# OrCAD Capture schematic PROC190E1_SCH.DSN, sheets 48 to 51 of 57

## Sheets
48 48. TEMPERATURE SENSOR & BRD ID: size C; title: TEMPERATURE SENSORS & BOARD ID EEPROM
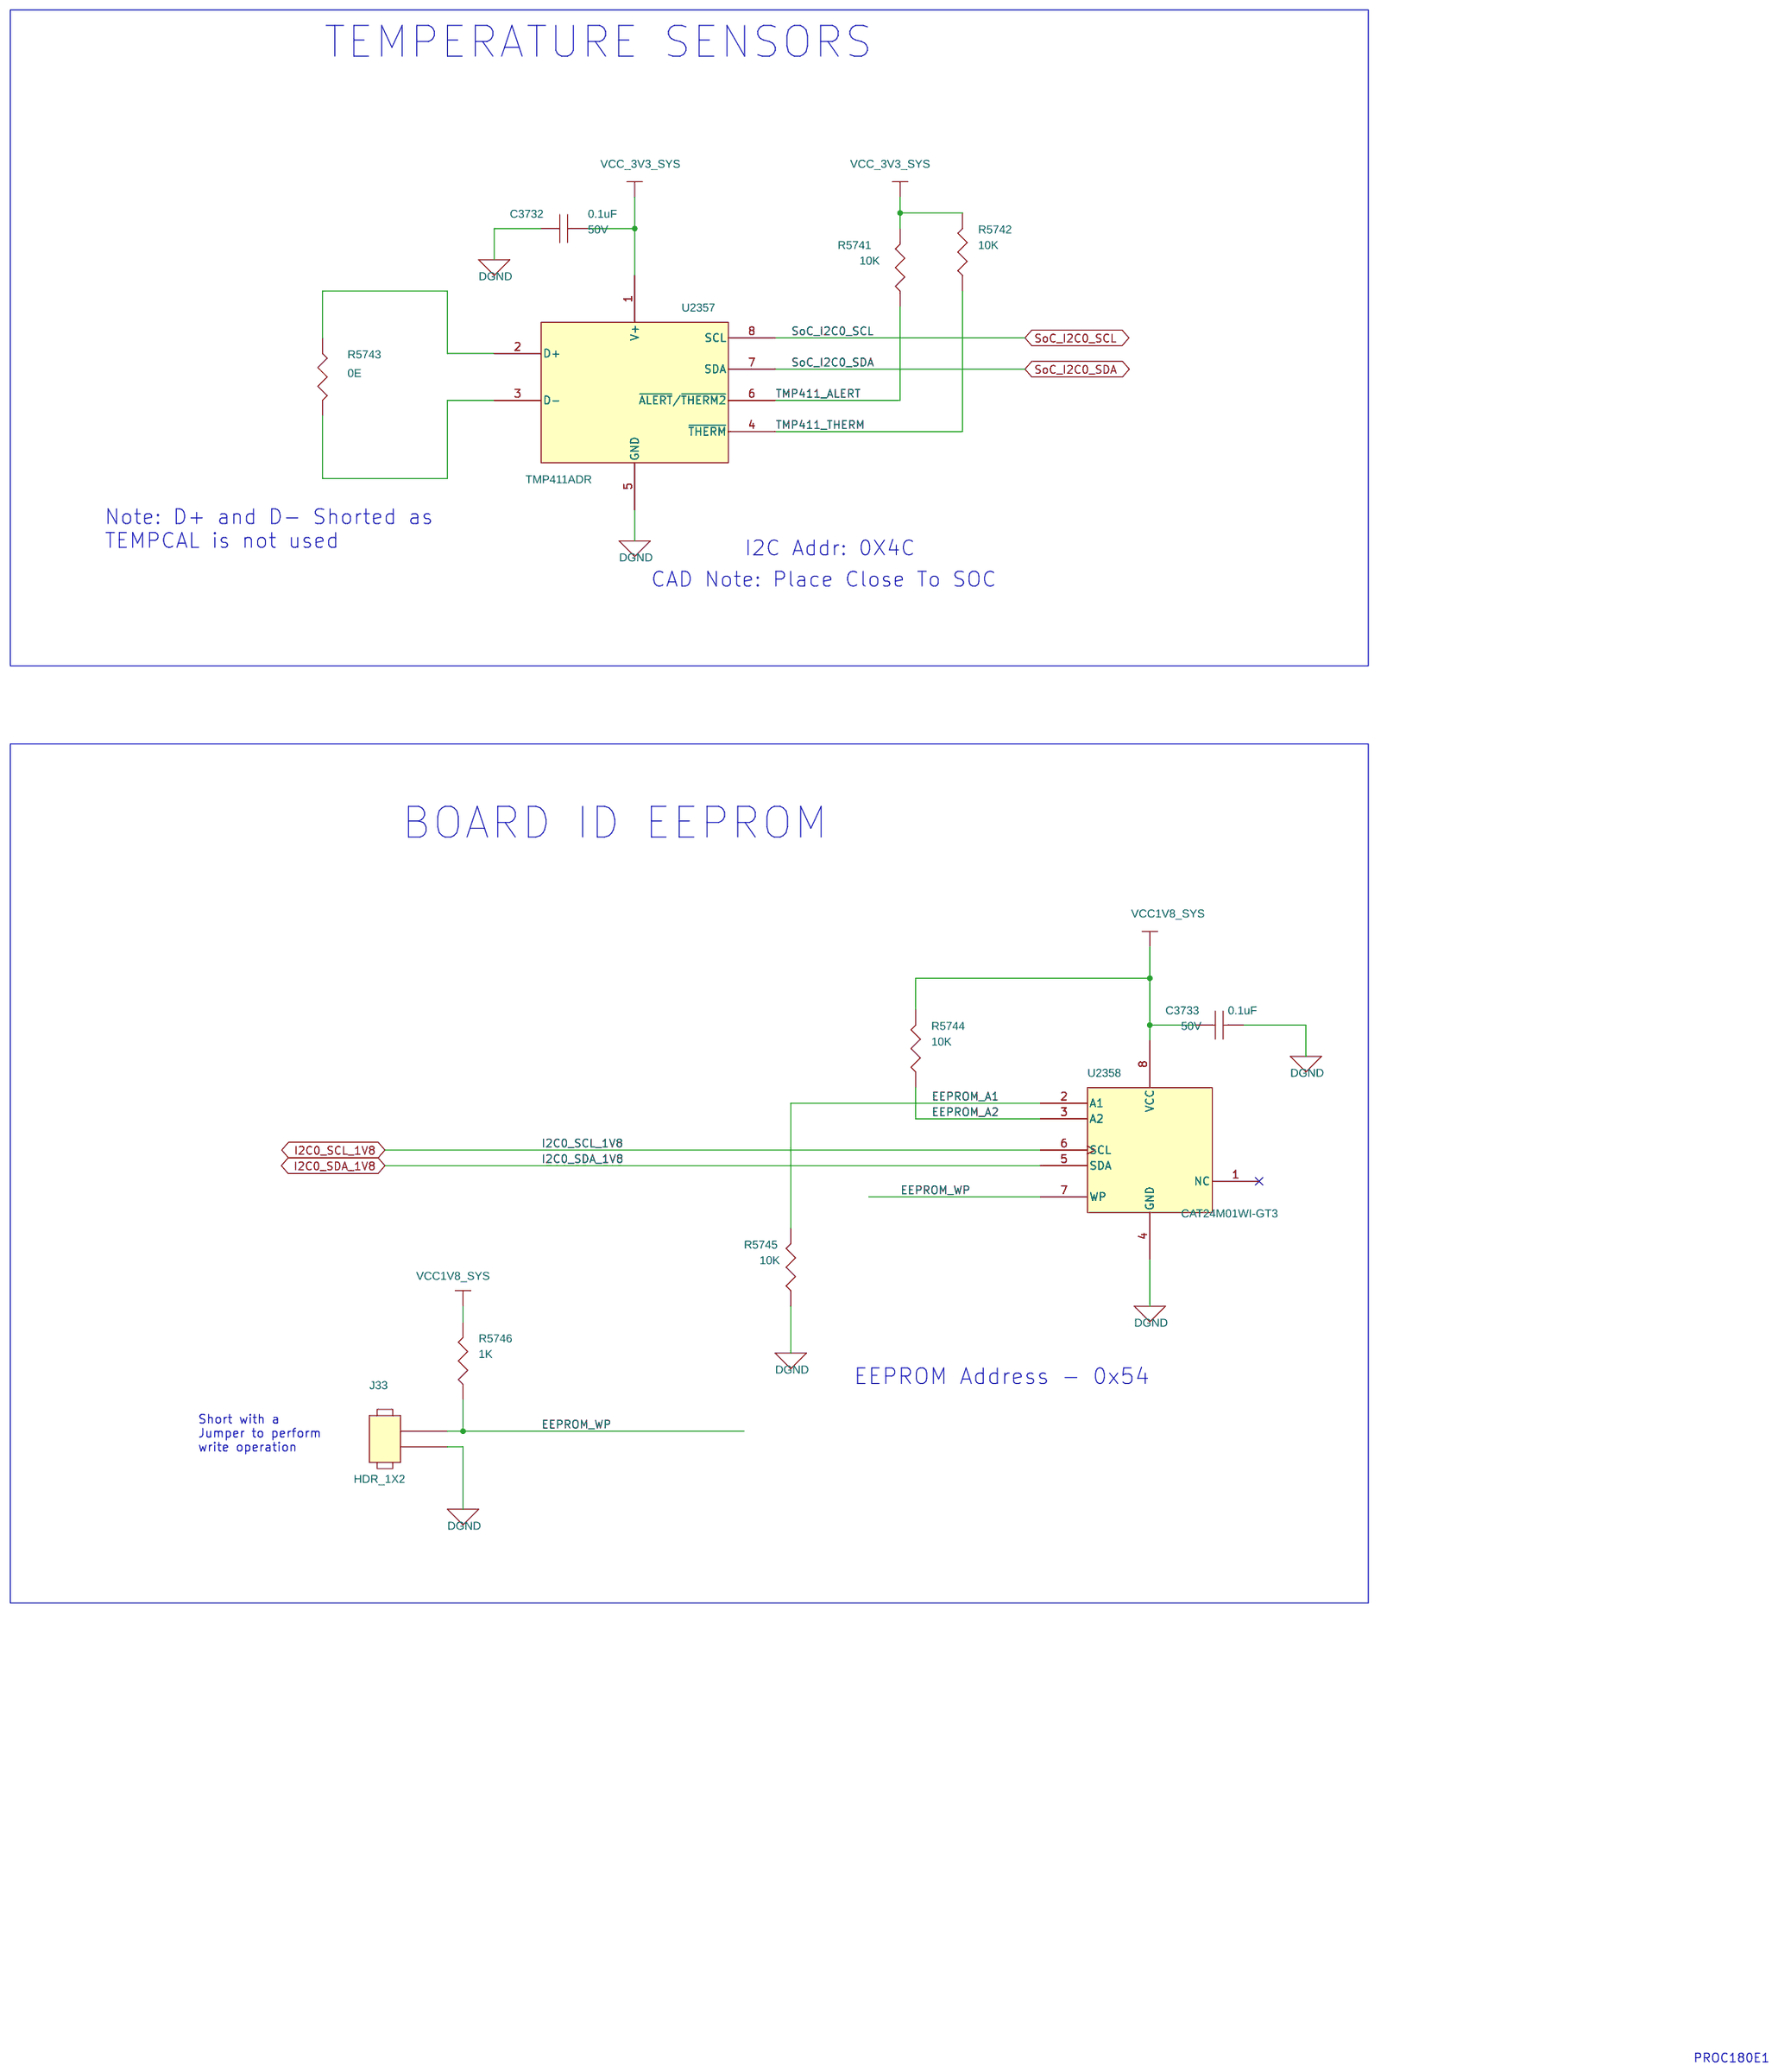
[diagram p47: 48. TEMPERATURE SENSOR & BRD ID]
49 49. CURRENT MONITORING - 1: size C; title: CURRENT MONITORING DEVICES - 1
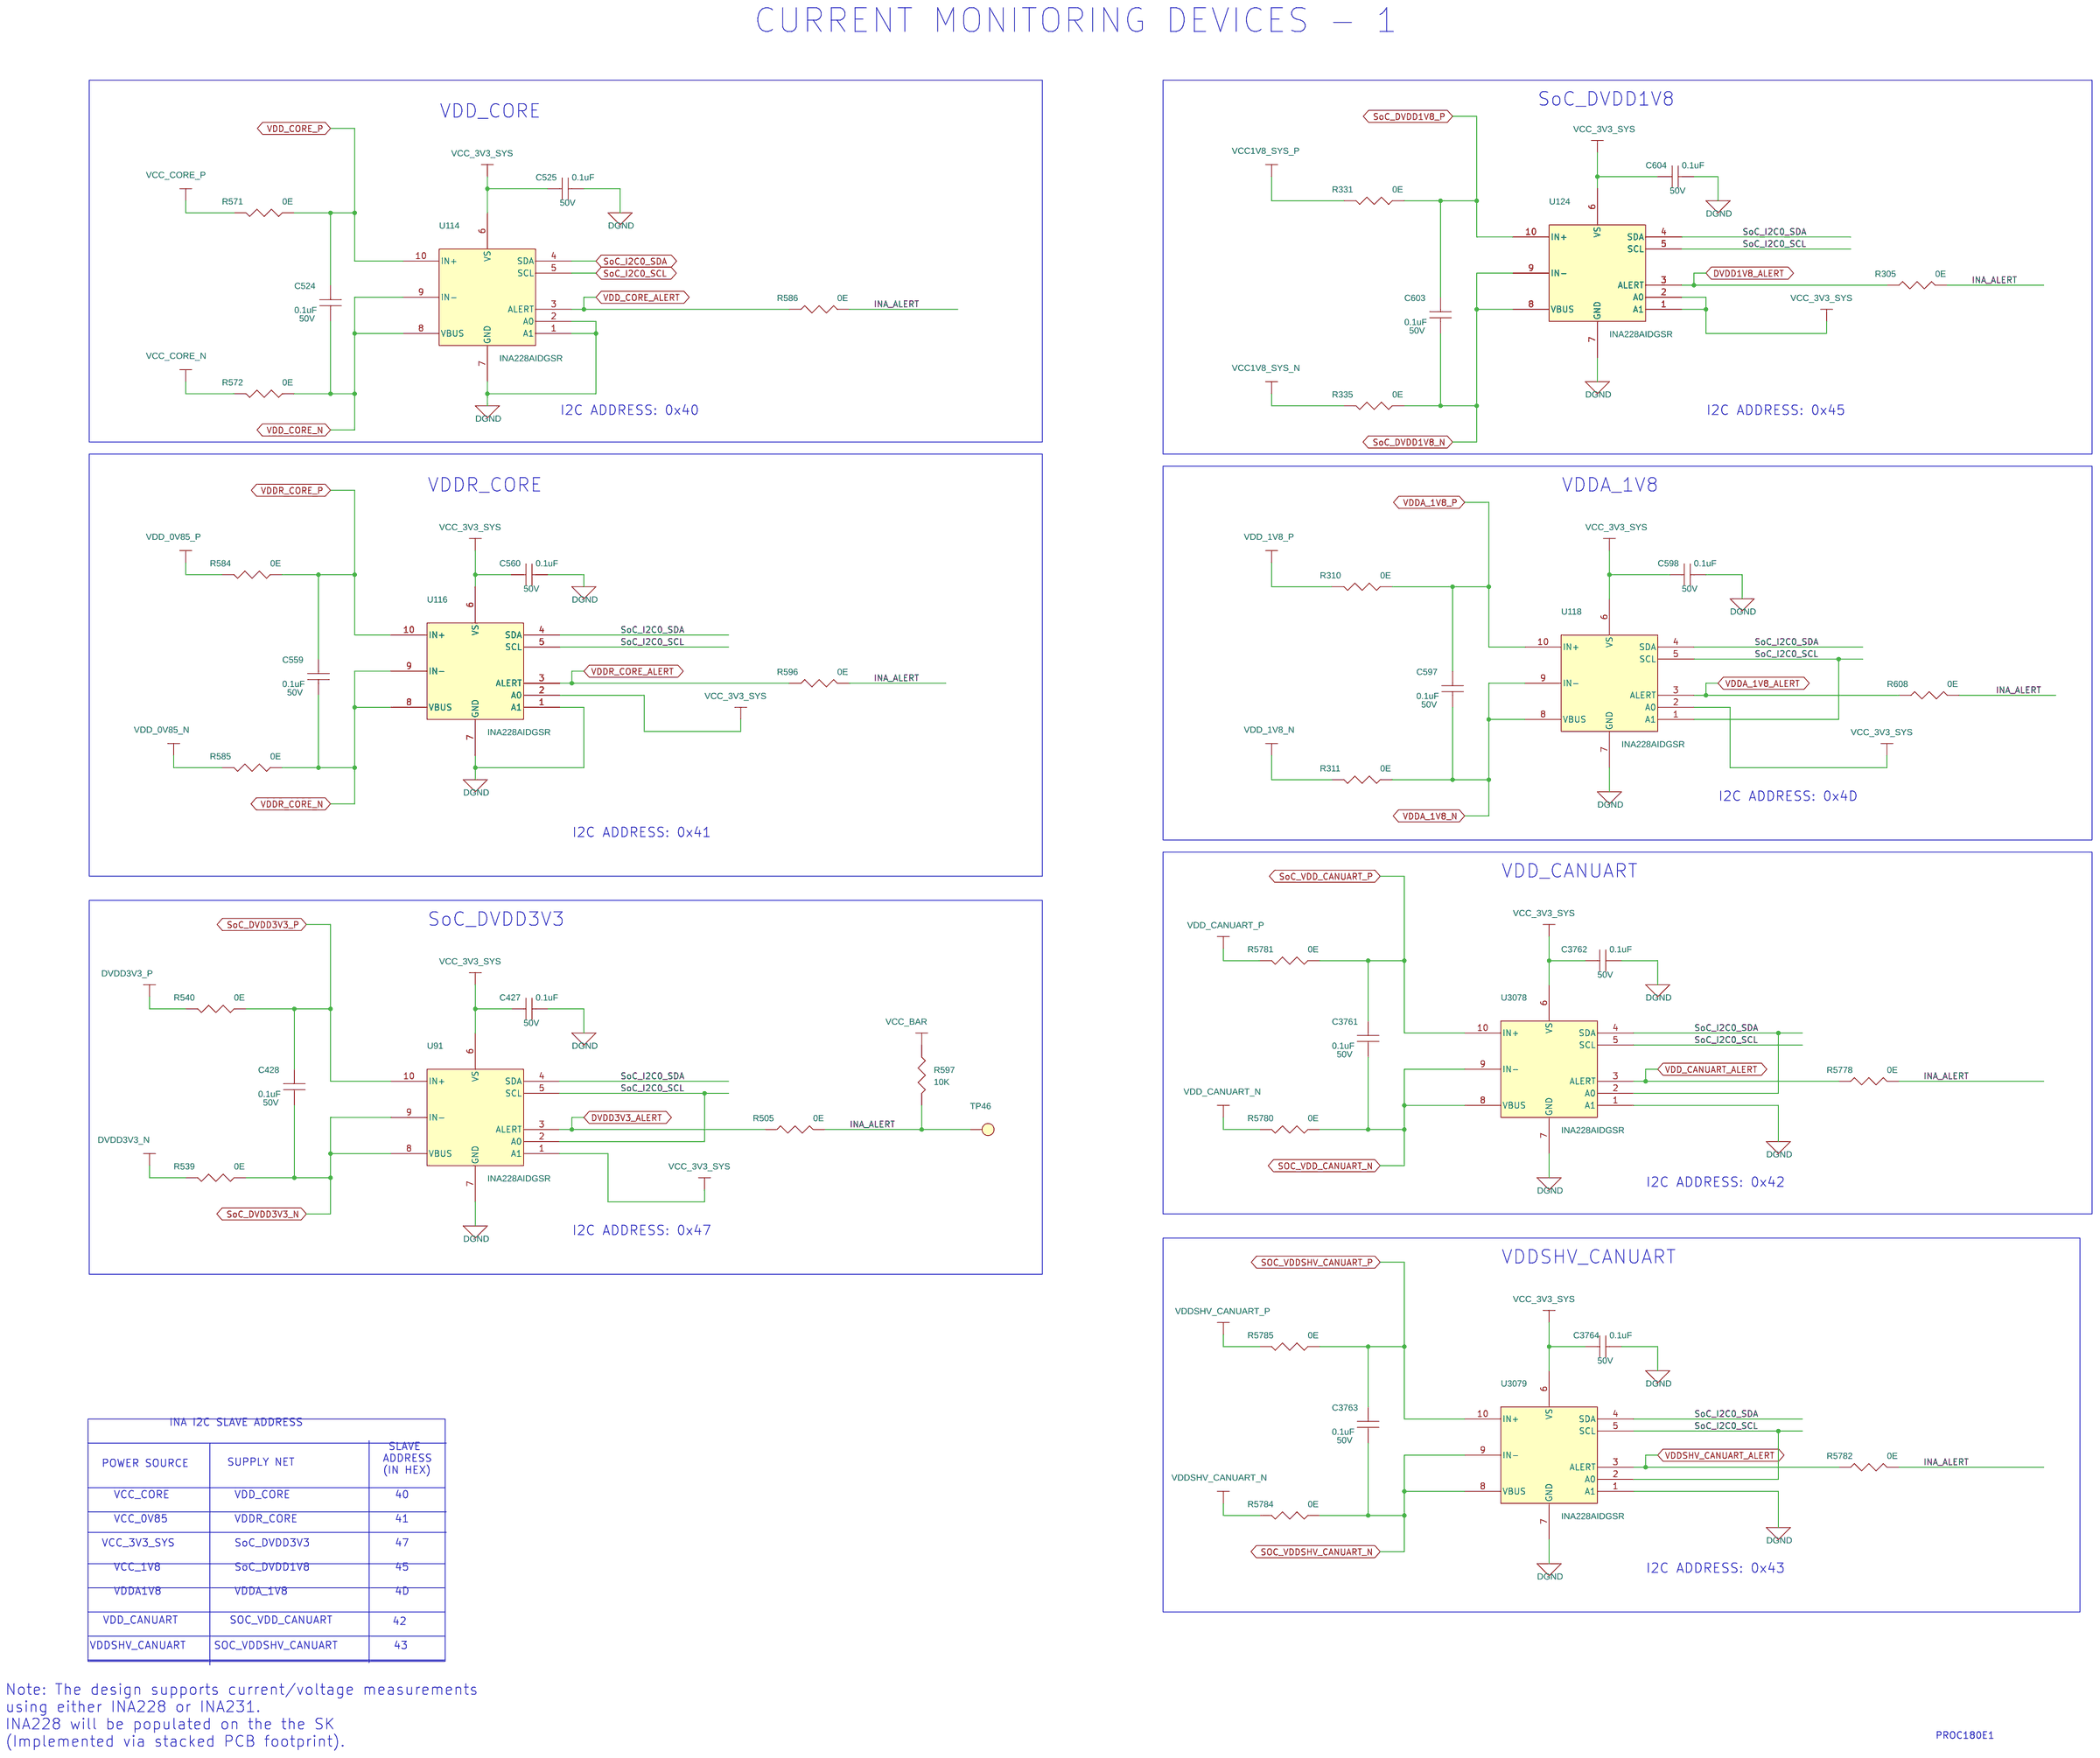
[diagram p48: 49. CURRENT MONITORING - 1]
50 50. CURRENT MONITORING - 2: size C; title: CURRENT MONITORING DEVICES - 2
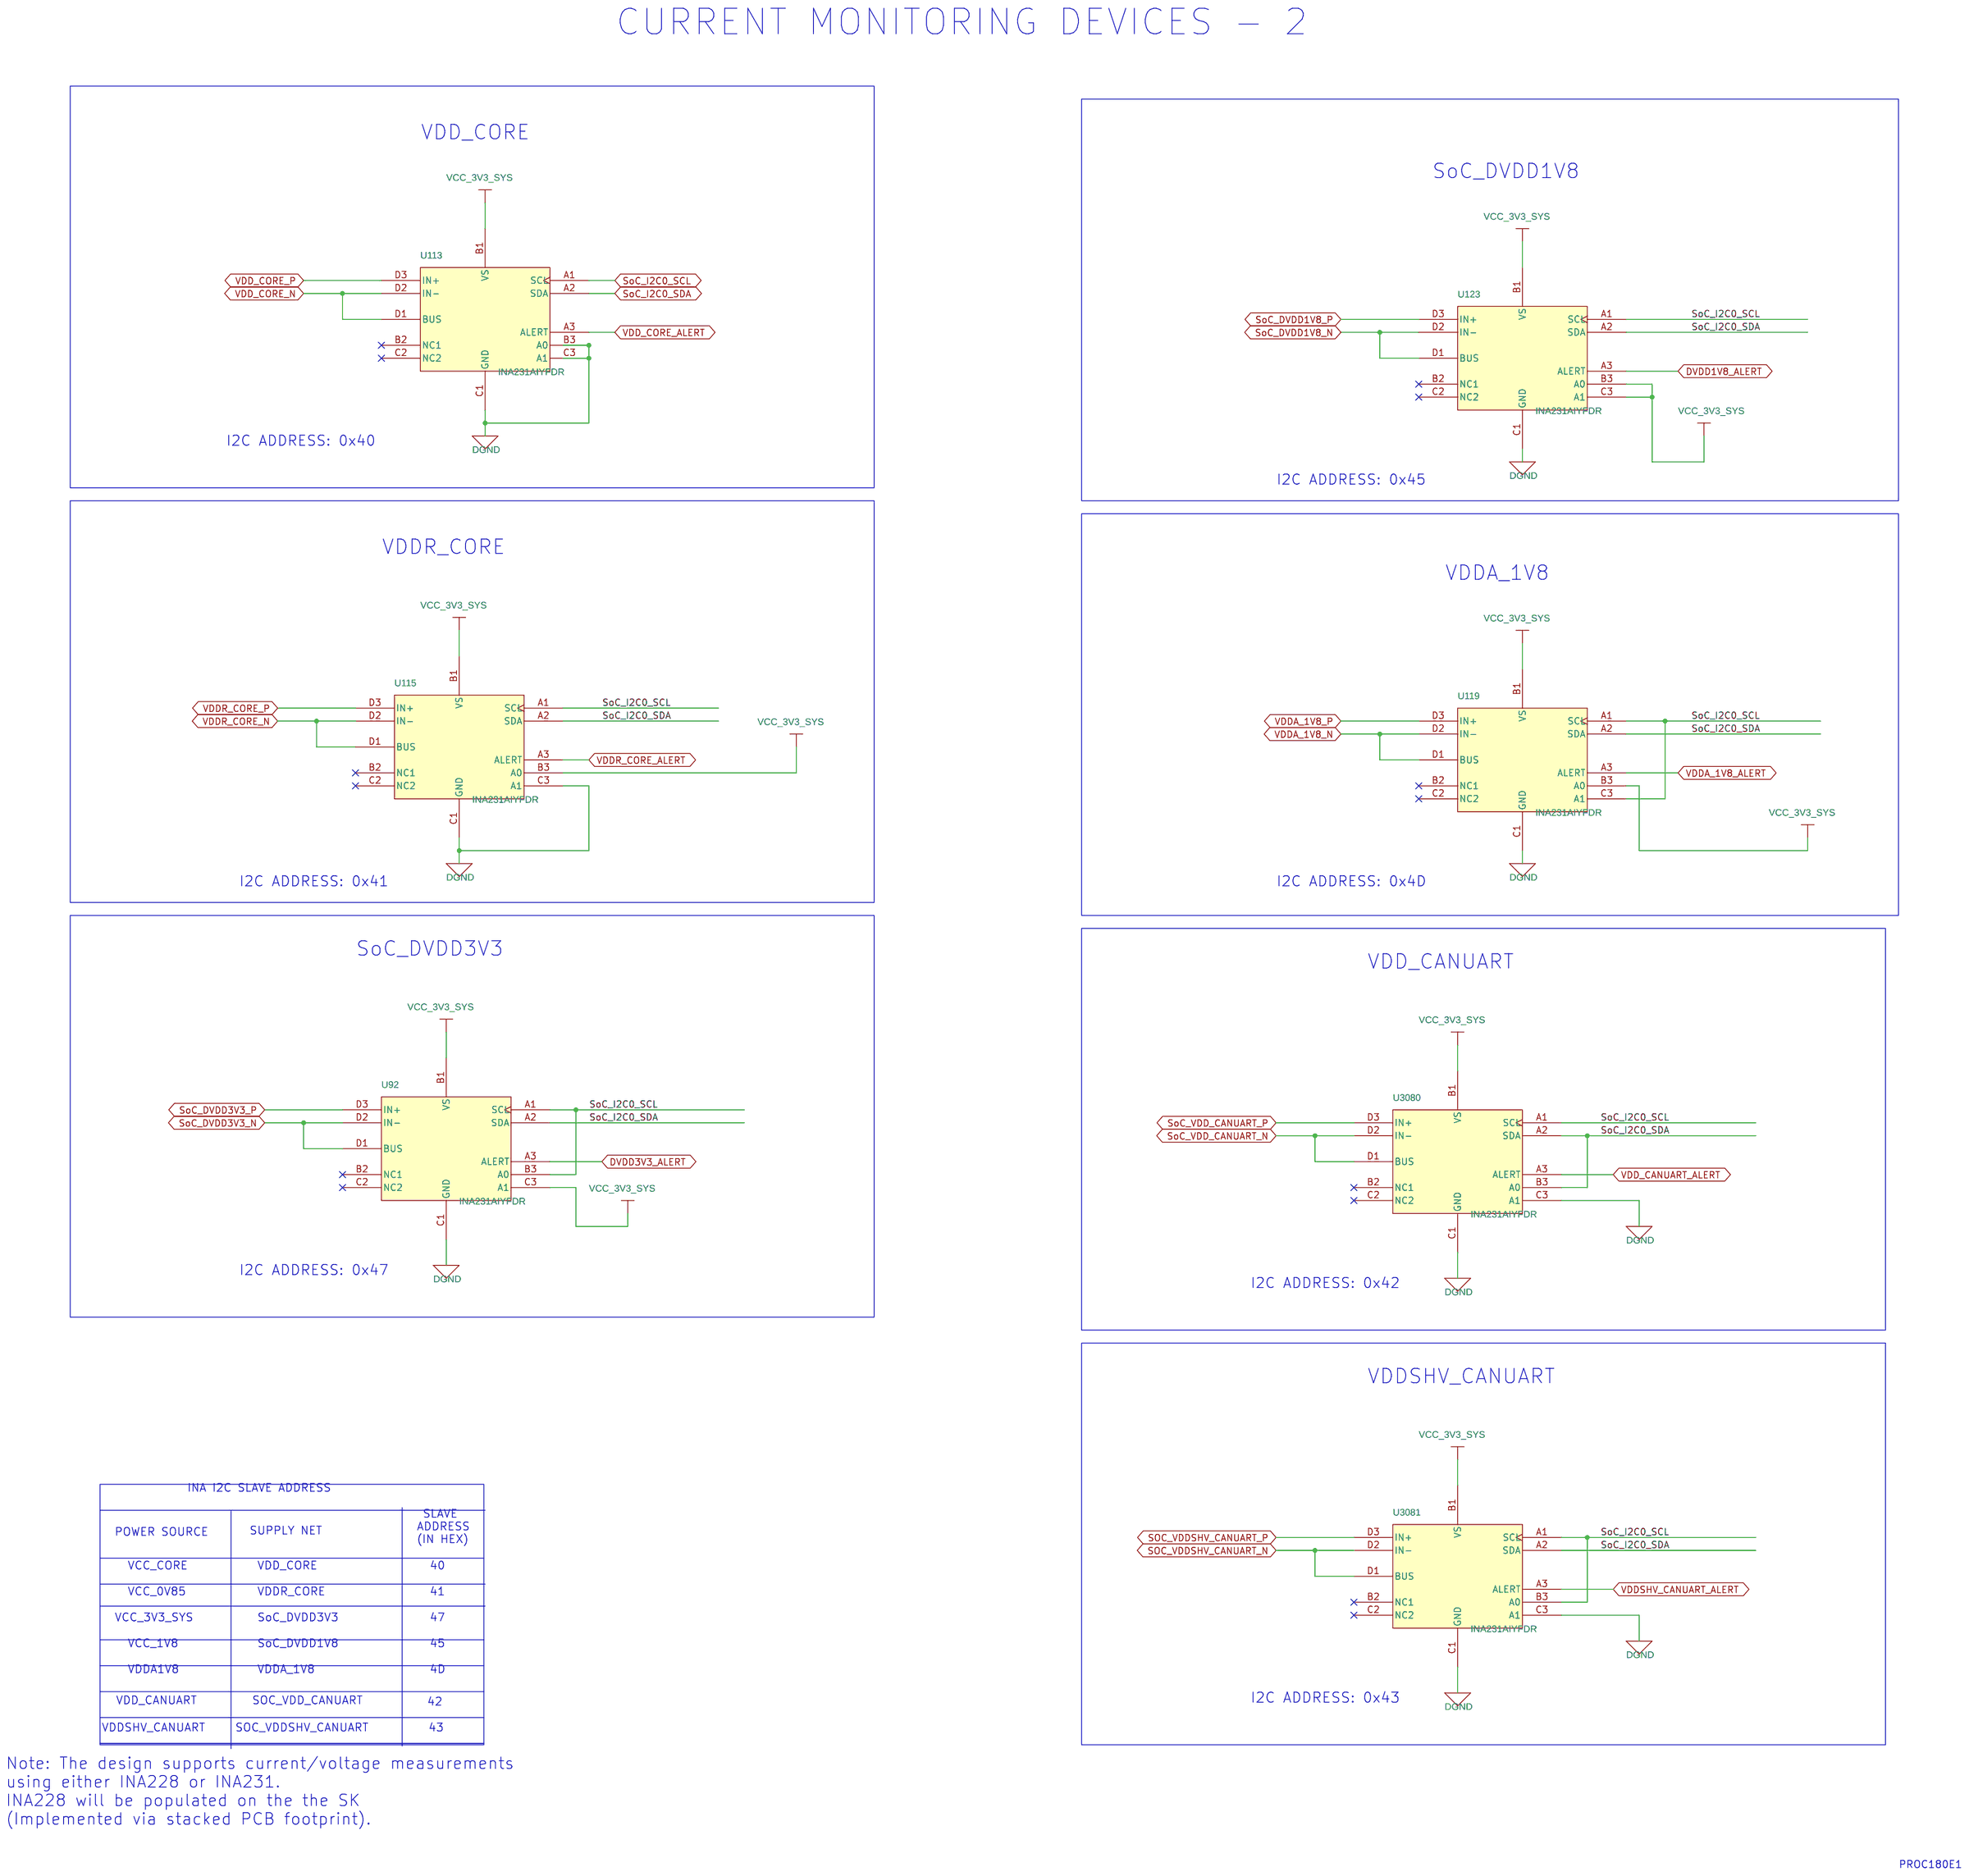
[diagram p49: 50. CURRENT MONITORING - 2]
51 51. FT4232 UART TO USB BRIDGE: size C; title: FT4232 UART TO USB BRIDGE
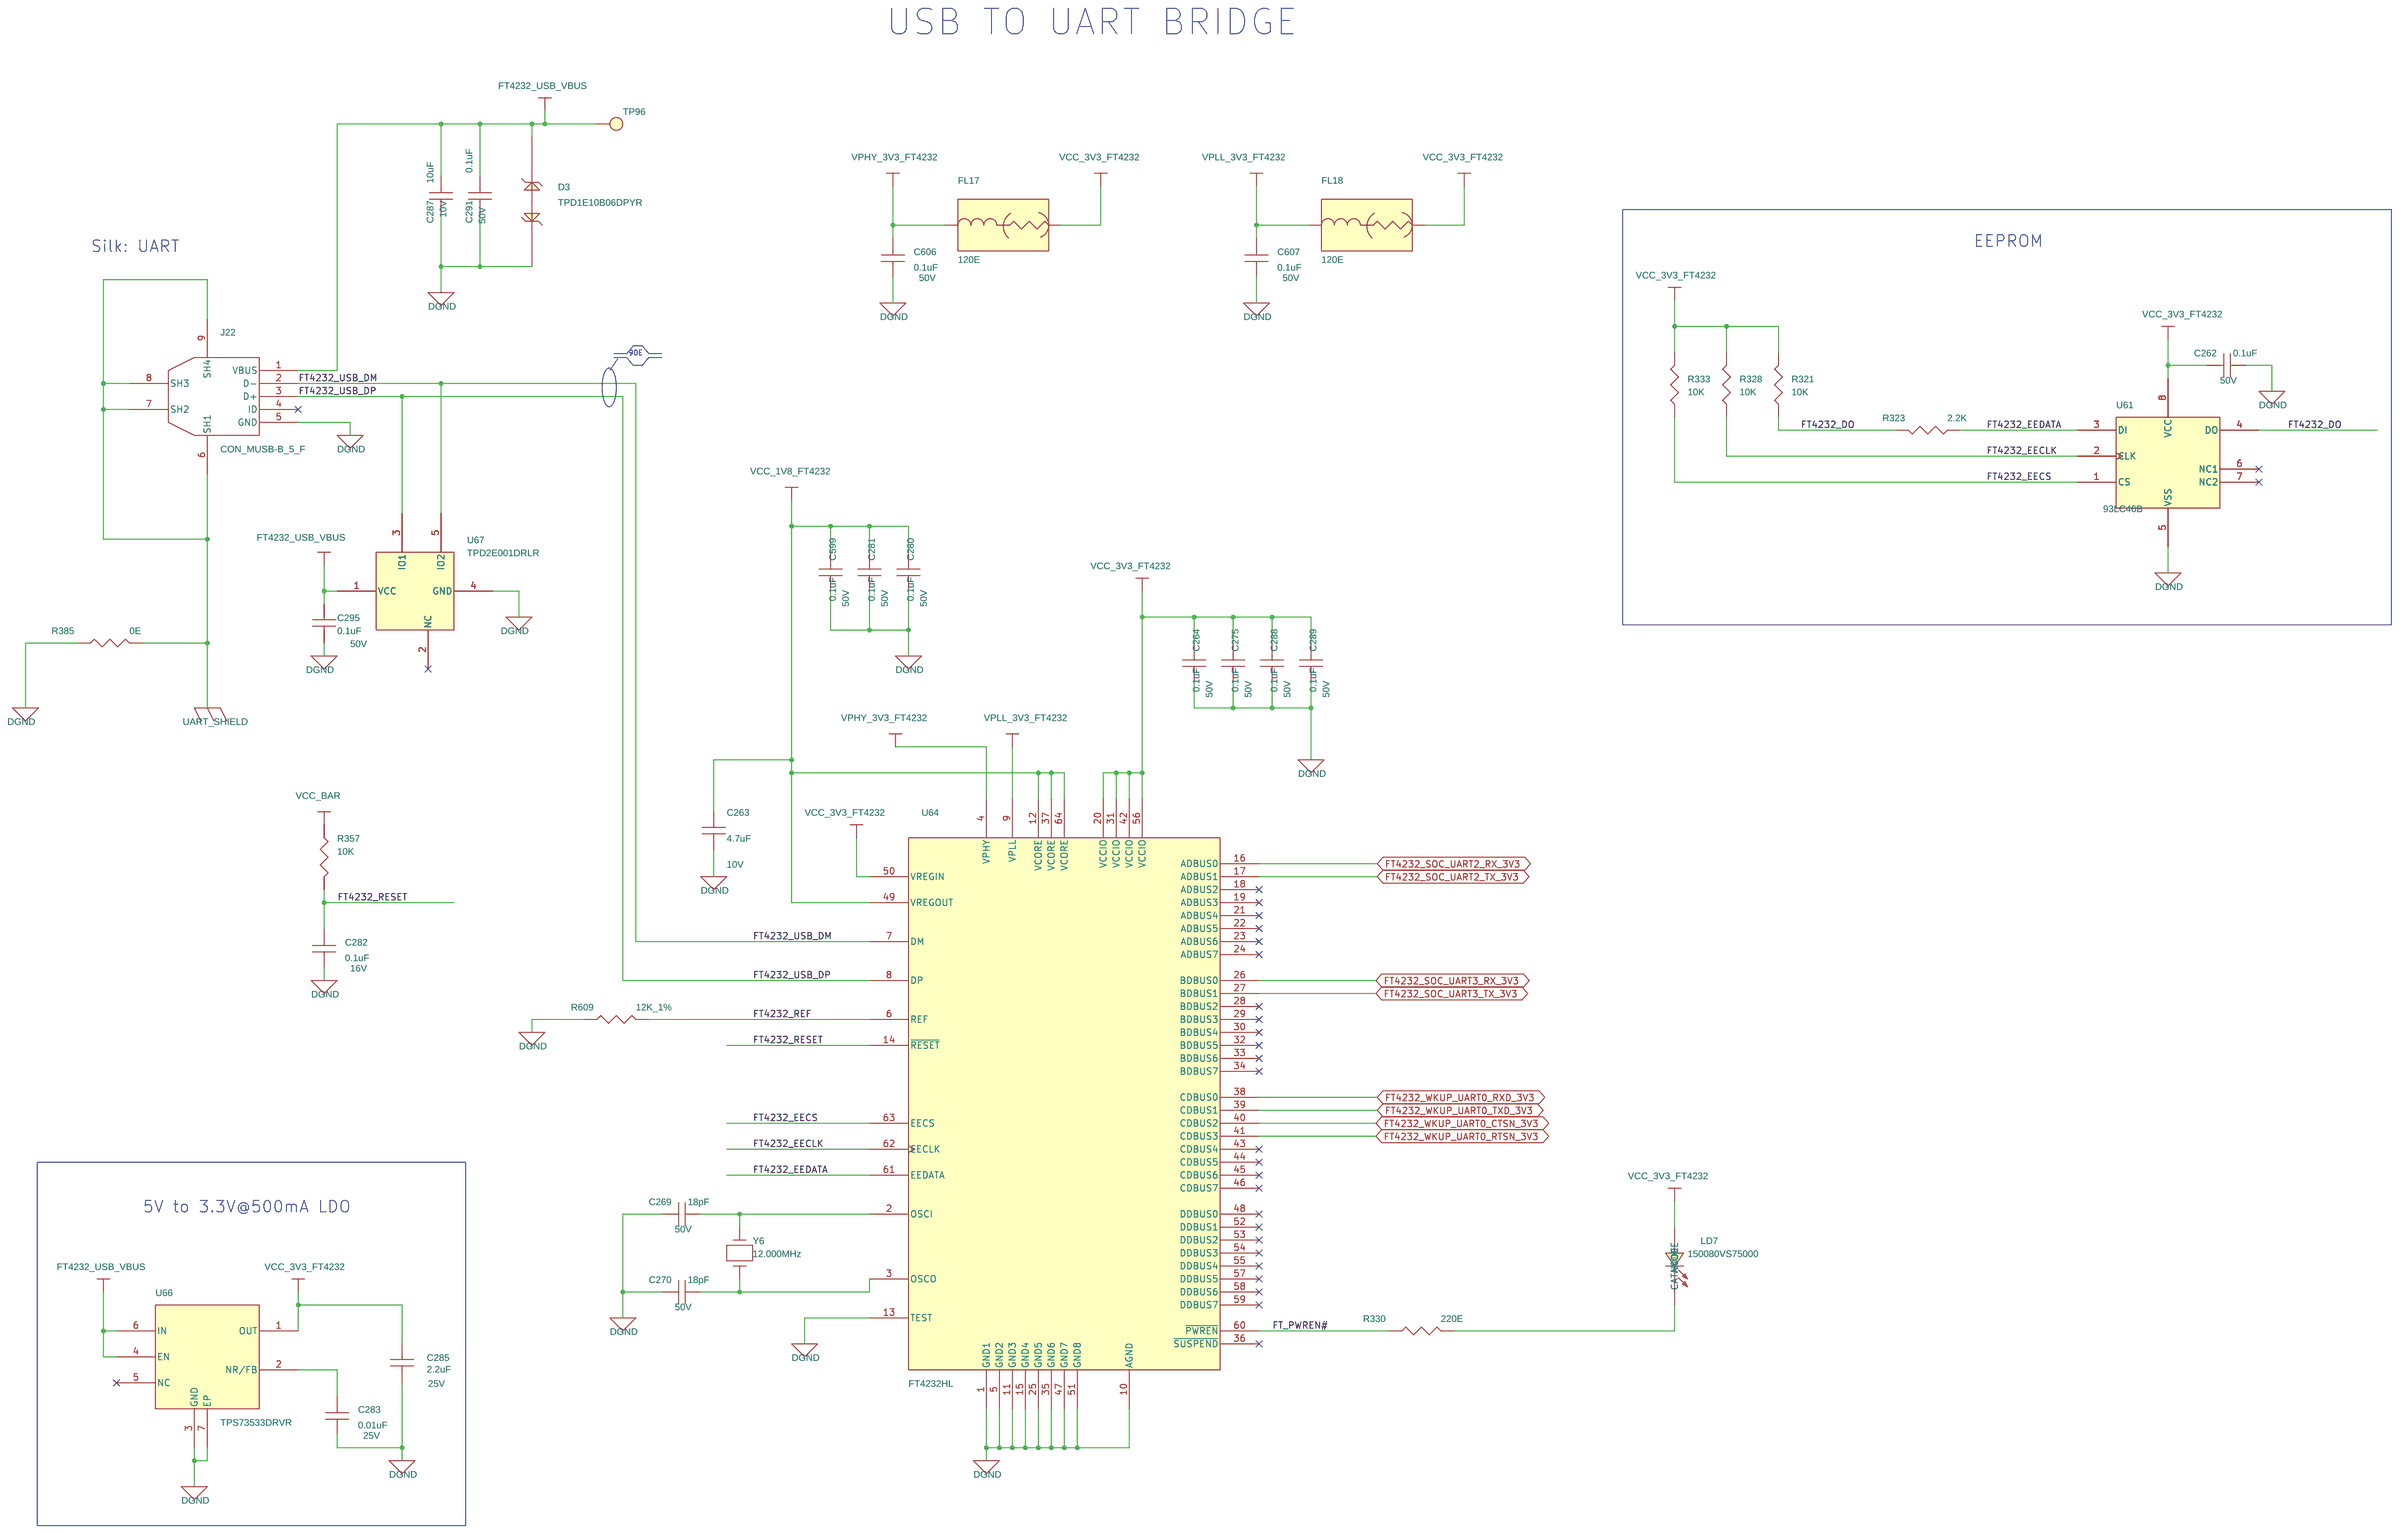
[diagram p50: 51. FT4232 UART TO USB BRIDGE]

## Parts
sheet 48. TEMPERATURE SENSOR & BRD ID
C3732  0.1uF  [CAP0402_0-75]
C3733  0.1uF  [CAP0402_0-75]
J33  HDR_1X2  [HDR_1X2_61300211121_S_T_8-6]
R5741  10K  [RES0402_0-5]
R5742  10K  [RES0402_0-5]
R5743  0E  [RES0402_0-5]
R5744  10K  [RES0402_0-5]
R5745  10K  [RES0402_0-5]
R5746  1K  [RES0402_0-5]
U2357  TMP411ADR  [SOIC8_1-8]
U2358  CAT24M01WI-GT3  [SOIC8_1-8]
sheet 49. CURRENT MONITORING - 1
C427  0.1uF  [CAP0402_0-75]
C428  0.1uF  [CAP0402_0-75]
C524  0.1uF  [CAP0402_0-75]
C525  0.1uF  [CAP0402_0-75]
C559  0.1uF  [CAP0402_0-75]
C560  0.1uF  [CAP0402_0-75]
C597  0.1uF  [CAP0402_0-75]
C598  0.1uF  [CAP0402_0-75]
C603  0.1uF  [CAP0402_0-75]
C604  0.1uF  [CAP0402_0-75]
C3761  0.1uF  [CAP0402_0-75]
C3762  0.1uF  [CAP0402_0-75]
C3763  0.1uF  [CAP0402_0-75]
C3764  0.1uF  [CAP0402_0-75]
R305  0E  [RES0201_0-5]
R310  0E  [RES0402_0-5]
R311  0E  [RES0402_0-5]
R331  0E  [RES0402_0-5]
R335  0E  [RES0402_0-5]
R505  0E  [RES0201_0-5]
R539  0E  [RES0402_0-5]
R540  0E  [RES0402_0-5]
R571  0E  [RES0402_0-5]
R572  0E  [RES0402_0-5]
R584  0E  [RES0402_0-5]
R585  0E  [RES0402_0-5]
R586  0E  [RES0201_0-5]
R596  0E  [RES0201_0-5]
R597  10K  [RES0201_0-5]
R608  0E  [RES0201_0-5]
R5778  0E  [RES0201_0-5]
R5780  0E  [RES0402_0-5]
R5781  0E  [RES0402_0-5]
R5782  0E  [RES0201_0-5]
R5784  0E  [RES0402_0-5]
R5785  0E  [RES0402_0-5]
TP46  TP20_SMD  [TP20_SMD]
U91  INA228AIDGSR  [MSOP10_19-68_120X120_1-1]
U114  INA228AIDGSR  [MSOP10_19-68_120X120_1-1]
U116  INA228AIDGSR  [MSOP10_19-68_120X120_1-1]
U118  INA228AIDGSR  [MSOP10_19-68_120X120_1-1]
U124  INA228AIDGSR  [MSOP10_19-68_120X120_1-1]
U3078  INA228AIDGSR  [MSOP10_19-68_120X120_1-1]
U3079  INA228AIDGSR  [MSOP10_19-68_120X120_1-1]
sheet 50. CURRENT MONITORING - 2
U92  INA231AIYFDR  [DSBGA12_15-74_60X70_0-4]
U113  INA231AIYFDR  [DSBGA12_15-74_60X70_0-4]
U115  INA231AIYFDR  [DSBGA12_15-74_60X70_0-4]
U119  INA231AIYFDR  [DSBGA12_15-74_60X70_0-4]
U123  INA231AIYFDR  [DSBGA12_15-74_60X70_0-4]
U3080  INA231AIYFDR  [DSBGA12_15-74_60X70_0-4]
U3081  INA231AIYFDR  [DSBGA12_15-74_60X70_0-4]
sheet 51. FT4232 UART TO USB BRIDGE
C262  0.1uF  [CAP0402_0-75]
C263  4.7uF  [CAP0402_0-75]
C264  0.1uF  [CAP0402_0-75]
C269  18pF  [CAP0402_0-75]
C270  18pF  [CAP0402_0-75]
C275  0.1uF  [CAP0402_0-75]
C280  0.1uF  [CAP0402_0-75]
C281  0.1uF  [CAP0402_0-75]
C282  0.1uF  [CAP0201_0-5]
C283  0.01uF  [CAP0201_0-5]
C285  2.2uF  [CAP0402_0-75]
C287  10uF  [CAP0402_0-75]
C288  0.1uF  [CAP0402_0-75]
C289  0.1uF  [CAP0402_0-75]
C291  0.1uF  [CAP0402_0-75]
C295  0.1uF  [CAP0402_0-75]
C599  0.1uF  [CAP0402_0-75]
C606  0.1uF  [CAP0402_0-75]
C607  0.1uF  [CAP0402_0-75]
D3  TPD1E10B06DPYR  [DIO_DFN0402_0-5]
FL17  120E  [EMIFIL_BLM15A_0402_0-6]
FL18  120E  [EMIFIL_BLM15A_0402_0-6]
J22  CON_MUSB-B_5_F  [CON_MUSBB5_629105150521_S_R_S_2-7]
LD7  150080VS75000  [LED_150080VS75000_80X50_SMD_0-8]
R321  10K  [RES0201_0-5]
R323  2.2K  [RES0201_0-5]
R328  10K  [RES0201_0-5]
R330  220E  [RES0402_0-5]
R333  10K  [RES0201_0-5]
R357  10K  [RES0201_0-5]
R385  0E  [RES0805_0-75]
R609  12K_1%  [RES0402_0-5]
TP96  TP20_SMD  [TP20_SMD]
U61  93LC46B  [MSOP8_25-59_125X125_1-1]
U64  FT4232HL  [LQFP64_19-68_390X390_1-6]
U66  TPS73533DRVR  [SON6_25-59_85X85]
U67  TPD2E001DRLR  [SOT553-5_0-6]
Y6  12.000MHz  [XTAL_ABM3_205X130_SMD_1-4]

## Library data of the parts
C3732 = CAP: CAP CERAMIC 0.1uF 50V 10% X7R 0402; Automotive Alternate_mfr_name: TDK; Automotive Alternate_mfr_part_number: CGA2B3X7R1H104K050BB; Chkd/date: MANIRAJA/261020; Crtd /date: ALVY/211020; Custom_Duty: 15%; Customs_HS_Code: 85322990; Direct Alternate_mfr_name: TDK; Direct Alternate_mfr_part_number: C1005X7R1H104K050BE; Distributor_name: DIGIKEY; Distributor_part_number: 490-10700-1-ND; Footprint Path: Y:\MIS_DATABASE\Library\ALTIUM_TOOL\PCB_FOOTPRINTS\Altium_Footprint_Lib.PcbLib; Height: 0.55MM; Library Path: Y:\MIS_DATABASE\Library\ALTIUM_TOOL\SCHEMATICS_PARTS\MS_DISCRETE_Library.schlib; Mfr_name: MURATA; Mfr_part_number: GRM155R71H104KE14D; Mistral Part No: 120011100014-R; Package: 0402; Part_type: CAPACITORS\CERAMIC; Project: J7_CP; RoHS: RoHS; Temperature: -55°C+125°C; Tolerance: 10%; Voltage: 50V; Wattage: NA; Weight: 3.1mg; Datasheet: Y:\MIS_DATABASE\DATASHEETS\CAPACITORS\GRM155R71H104KE14.PDF
C3733 = CAP: CAP CERAMIC 0.1uF 50V 10% X7R 0402; Automotive Alternate_mfr_name: TDK; Automotive Alternate_mfr_part_number: CGA2B1X7R1C104K050BC; Chkd/date: MANIRAJA/261020; Crtd /date: ALVY/211020; Custom_Duty: 15%; Customs_HS_Code: 85322990; Direct Alternate_mfr_name: MURATA; Direct Alternate_mfr_part_number: GCM155R71C104JA55D; Distributor_name: DIGIKEY; Distributor_part_number: 490-10700-1-ND; Footprint Path: Y:\MIS_DATABASE\Library\ALTIUM_TOOL\PCB_FOOTPRINTS\Altium_Footprint_Lib.PcbLib; Height: 0.55MM; Library Path: Y:\MIS_DATABASE\Library\ALTIUM_TOOL\SCHEMATICS_PARTS\MS_DISCRETE_Library.schlib; Mfr_name: MURATA; Mfr_part_number: GRM155R71H104KE14D; Mistral Part No: 120011100014-R; Package: 0402; Part_type: CAPACITORS\CERAMIC; Project: J7_CP; RoHS: RoHS; Temperature: -55°C+125°C; Tolerance: 10%; Voltage: 50V; Wattage: NA; Weight: 3.1mg; Datasheet: Y:\MIS_DATABASE\DATASHEETS\CAPACITORS\GRM155R71H104KE14.PDF
J33 = HEADER_2X1: CON HDR 1X2 2.54MM PITCH ST TH; Chkd/date: MANIRAJA/031018; Crtd /date: ALVY/031018; Custom_Duty: 24%; Customs_HS_Code: 85369090; Distributor_name: DIGIKEY; Distributor_part_number: 732-5315-ND; Footprint Path: Y:\MIS_DATABASE\Library\ALTIUM_TOOL\PCB_FOOTPRINTS\Altium_Footprint_Lib.PcbLib; Height: 8.54MM; Library Path: Y:\MIS_DATABASE\Library\ALTIUM_TOOL\SCHEMATICS_PARTS\MS_CONNECTOR_Library.schlib; Mfr_name: WURTH ELECTRONICS; Mfr_part_number: 61300211121; Mistral Part No: 150018100003-R; Package: THRU-HOLE; Part_type: CONNECTOR\HEADERS; Project: ALPINE_EVM; RoHS: RoHS; Temperature: -40°C+105°C; Tolerance: NA; Voltage: NA; Wattage: NA; Weight: 120mg; Datasheet: Y:\MIS_DATABASE\DATASHEETS\CONNECTORS\6130XXX.PDF
R5741 R5742 = RESISTOR: RES 10K 1/16W 5% 0402; Assembly_Instruction: DNI; Chkd/date: VASANTHA/061216; Crtd /date: MAZHAR/230805; Custom_Duty: 15%; Customs_HS_Code: 85332119; Distributor_name: DIGIKEY; Distributor_part_number: 311-10KJRCT-ND; Footprint Path: Y:\MIS_DATABASE\Library\ALTIUM_TOOL\PCB_FOOTPRINTS\Altium_Footprint_Lib.PcbLib; Height: 0.40MM; Library Path: Y:\MIS_DATABASE\Library\ALTIUM_TOOL\SCHEMATICS_PARTS\MS_DISCRETE_Library.schlib; Mfr_name: YAGEO AMERICA; Mfr_part_number: RC0402JR-0710KL; Mistral Part No: 110011060021-R; Package: 0402; Part_type: RESISTORS\FIXED; Project: HSE; RoHS: RoHS; Temperature: -55°C+155°C; Tolerance: 5%; Voltage: NA; Wattage: 1/16W; Weight: 0.65mg; Datasheet: Y:\MIS_DATABASE\DATASHEETS\RESISTORS\RCXXXXL-SER_MAR18.PDF
R5743 = RESISTOR: RES 0E 1/10W JUMPER 0402; Chkd/date: VASANTHA/061216; Crtd /date: NAVEED/201014; Custom_Duty: 15%; Customs_HS_Code: 85332119; Distributor_name: DIGIKEY; Distributor_part_number: P0.0JCT-ND; Footprint Path: Y:\MIS_DATABASE\Library\ALTIUM_TOOL\PCB_FOOTPRINTS\Altium_Footprint_Lib.PcbLib; Height: 0.40MM; IBISSP_MODLES: VALUE REPEATING 2 TIME; Library Path: Y:\MIS_DATABASE\Library\ALTIUM_TOOL\SCHEMATICS_PARTS\MS_DISCRETE_Library.schlib; Mfr_name: PANASONIC-ECG; Mfr_part_number: ERJ-2GE0R00X; Mistral Part No: 110018030052-R; Package: 0402; Part_type: RESISTORS\FIXED; Project: AEGIS POM; RoHS: RoHS; Temperature: -55°C+155°C; Tolerance: NA; Voltage: NA; Wattage: 1/10W; Weight: 0.8mg; Datasheet: Y:\MIS_DATABASE\DATASHEETS\RESISTORS\PAN-ERJSER_NOV17.PDF
R5744 R5745 = RESISTOR: RES 10K 1/16W 5% 0402; Chkd/date: VASANTHA/061216; Crtd /date: MAZHAR/230805; Custom_Duty: 15%; Customs_HS_Code: 85332119; Distributor_name: DIGIKEY; Distributor_part_number: 311-10KJRCT-ND; Footprint Path: Y:\MIS_DATABASE\Library\ALTIUM_TOOL\PCB_FOOTPRINTS\Altium_Footprint_Lib.PcbLib; Height: 0.40MM; Library Path: Y:\MIS_DATABASE\Library\ALTIUM_TOOL\SCHEMATICS_PARTS\MS_DISCRETE_Library.schlib; Mfr_name: YAGEO AMERICA; Mfr_part_number: RC0402JR-0710KL; Mistral Part No: 110011060021-R; Package: 0402; Part_type: RESISTORS\FIXED; Project: HSE; RoHS: RoHS; Temperature: -55°C+155°C; Tolerance: 5%; Voltage: NA; Wattage: 1/16W; Weight: 0.65mg; Datasheet: Y:\MIS_DATABASE\DATASHEETS\RESISTORS\RCXXXXL-SER_MAR18.PDF
R5746 = RESISTOR: RES 1K 1/10W 5% 0402; Chkd/date: VASANTHA/201216; Crtd /date: MAZHAR/230805; Custom_Duty: 15%; Customs_HS_Code: 85332119; Distributor_name: DIGIKEY; Distributor_part_number: P1.0KJCT-ND; Footprint Path: Y:\MIS_DATABASE\Library\ALTIUM_TOOL\PCB_FOOTPRINTS\Altium_Footprint_Lib.PcbLib; Height: 0.40MM; Library Path: Y:\MIS_DATABASE\Library\ALTIUM_TOOL\SCHEMATICS_PARTS\MS_DISCRETE_Library.schlib; Mfr_name: PANASONIC-ECG; Mfr_part_number: ERJ-2GEJ102X; Mistral Part No: 110009030400-R; Package: 0402; Part_type: RESISTORS\FIXED; Project: HSE; RoHS: RoHS; Temperature: -55°C+155°C; Tolerance: 5%; Voltage: NA; Wattage: 1/10W; Weight: 0.8mg; Datasheet: Y:\MIS_DATABASE\DATASHEETS\RESISTORS\PAN-ERJSER_NOV17.PDF
U2357 = TMP411ADR_SOIC8: IC REMOTE AND LOCAL TEMPERATURE SENSOR WITH N-FACTOR AND SERIES RESISTANCE CORRECTION SOIC8; Chkd/date: ALVY/070521; Crtd /date: MANIRAJA/070521; Custom_Duty: 15%; Customs_HS_Code: 85423100; Distributor_name: DIGIKEY; Distributor_part_number: 296-47859-2-ND; Footprint Path: Y:\MIS_DATABASE\Library\ALTIUM_TOOL\PCB_FOOTPRINTS\Altium_Footprint_Lib.PcbLib; Height: 1.75MM; Library Path: Y:\MIS_DATABASE\Library\ALTIUM_TOOL\SCHEMATICS_PARTS\MS_COMBINATIONAL_Library.schlib; Mfr_name: TEXAS INSTRUMENTS; Mistral Part No: 141021050005-R; Package: SOIC8; Part_type: ICS\DIGITAL\PERIPHERAL; Project: AM263x_CC; RoHS: RoHS; Temperature: -40°C+125°C; Tolerance: NA; Voltage: NA; Wattage: NA; Weight: 76mg; Datasheet: Y:\MIS_DATABASE\DATASHEETS\ICS\DIGITAL\PERIPHERAL\TMP411XXX.PDF
U2358 = AT24HC04B-TH-B_TSSOP8: IC 1Mb I2C SERIAL EEPROM SOIC8; Chkd/date: ALVY/230621; Crtd /date: ALVY/230621; Custom_Duty: 15%; Customs_HS_Code: 85423100; Distributor_name: DIGIKEY; Distributor_part_number: CAT24M01WI-GT3OSCT-ND; Footprint Path: Y:\MIS_DATABASE\Library\ALTIUM_TOOL\PCB_FOOTPRINTS\Altium_Footprint_Lib.PcbLib; Height: 1.75MM; Library Path: Y:\MIS_DATABASE\Library\ALTIUM_TOOL\SCHEMATICS_PARTS\MS_MISCMEMORY_Library.schlib; Mfr_name: ON SEMICONDUCTOR; Mistral Part No: 141121060004-R; Package: SOIC8; Part_type: ICS\DIGITAL\MEMORY; Project: AM263x_CC; RoHS: RoHS; Temperature: -40°C+85°C; Tolerance: NA; Voltage: NA; Wattage: NA; Weight: 540mg; Datasheet: Y:\MIS_DATABASE\DATASHEETS\ICS\MEMORY\CAT24M01.PDF
C262 C264 C275 C280 C281 C288 C289 C291 C295 C427 C428 C524 C525 C559 C560 C597-C599 C603 C604 C606 C607 C3761-C3764 = CAP: CAP CERAMIC 0.1uF 50V 10% X7R AUTO 0402; Alt_Mfr_name: YAGEO AMERICA; Alt_Mfr_part_number: CC0402KRX5R8BB104; Chkd/date: MANIRAJA/250221; Crtd /date: ALVY/240221; Custom_Duty: 15%; Customs_HS_Code: 85322990; Distributor_name: MOUSER; Distributor_part_number: 81-GRT155R71H104KE1D; Footprint Path: Y:\MIS_DATABASE\Library\ALTIUM_TOOL\PCB_FOOTPRINTS\Altium_Footprint_Lib.PcbLib; Height: 0.55MM; Library Path: Y:\MIS_DATABASE\Library\ALTIUM_TOOL\SCHEMATICS_PARTS\MS_DISCRETE_Library.schlib; Mfr_name: MURATA; Mfr_part_number: GRT155R71H104KE01D; Mistral Part No: 120019030005-R; Package: 0402; Part_type: CAPACITORS\CERAMIC; Project: TI_DRA821 SK EVM BRD; RoHS: RoHS; Temperature: -55°C+125°C; Tolerance: 10%; Voltage: 50V; Wattage: NA; Weight: NA; Datasheet: Y:\MIS_DATABASE\DATASHEETS\CAPACITORS\GRT155R71H104KE01.PDF
R305 R505 R586 R596 R608 R5778 R5782 = RESISTOR: RES 0E 1/20W 5% 0201; Chkd/date: NAVEED/301214; Crtd /date: MUDDU/120710; Custom_Duty: 15%; Customs_HS_Code: 85332119; Distributor_name: DIGIKEY; Distributor_part_number: 311-0.0NCT-ND; Footprint Path: Y:\MIS_DATABASE\Library\ALTIUM_TOOL\PCB_FOOTPRINTS\Altium_Footprint_Lib.PcbLib; Height: 0.26MM; Library Path: Y:\MIS_DATABASE\Library\ALTIUM_TOOL\SCHEMATICS_PARTS\MS_DISCRETE_Library.schlib; Mfr_name: YAGEO AMERICA; Mfr_part_number: RC0201JR-070RL; Mistral Part No: 110010070067-R; Package: 0201; Part_type: RESISTORS\FIXED; Project: PB_BUGBASE; RoHS: RoHS; Temperature: -55°C+125°C; Tolerance: 5%; Voltage: NA; Wattage: 1/20W; Weight: 0.17mg; Datasheet: Y:\MIS_DATABASE\DATASHEETS\RESISTORS\RCXXXXL-SER_MAR18.PDF
R310 R311 R331 R335 R539 R540 R571 R572 R584 R585 R5780 R5781 R5784 R5785 = RESISTOR: RES 0E 1/16W JUMPER 0402; Chkd/date: VASANTHA/201216; Crtd /date: MUDDU/190810; Custom_Duty: 15%; Customs_HS_Code: 85332119; Distributor_name: DIGIKEY; Distributor_part_number: 541-0.0JCT-ND; Footprint Path: Y:\MIS_DATABASE\Library\ALTIUM_TOOL\PCB_FOOTPRINTS\Altium_Footprint_Lib.PcbLib; Height: 0.40MM; Library Path: Y:\MIS_DATABASE\Library\ALTIUM_TOOL\SCHEMATICS_PARTS\MS_DISCRETE_Library.schlib; Mfr_name: VISHAY; Mfr_part_number: CRCW04020000Z0ED; Mistral Part No: 110010080019-R; Package: 0402; Part_type: RESISTORS\FIXED; Project: PB_BUGBASE; RoHS: RoHS; Temperature: -55°C+155°C; Tolerance: NA; Voltage: NA; Wattage: 1/16W; Weight: 0.65mg; Datasheet: Y:\MIS_DATABASE\DATASHEETS\RESISTORS\CRCW0603.PDF
R321 R328 R333 R357 R597 = RESISTOR: RES 10K 1/20W 5% 0201; Chkd/date: MANIRAJA/050517; Crtd /date: MANIRAJA/050517; Custom_Duty: 15%; Customs_HS_Code: 85332119; Distributor_name: DIGIKEY; Distributor_part_number: 311-10KNCT-ND; Footprint Path: Y:\MIS_DATABASE\Library\ALTIUM_TOOL\PCB_FOOTPRINTS\Altium_Footprint_Lib.PcbLib; Height: 0.26MM; Library Path: Y:\MIS_DATABASE\Library\ALTIUM_TOOL\SCHEMATICS_PARTS\MS_DISCRETE_Library.schlib; Mfr_name: YAGEO AMERICA; Mfr_part_number: RC0201JR-0710KL; Mistral Part No: 110010070051-R; Package: 0201; Part_type: RESISTORS\FIXED; Project: GOLDEN-I LITE; RoHS: RoHS; Temperature: -55°C+125°C; Tolerance: 5%; Voltage: NA; Wattage: 1/20W; Weight: 0.17mg; Datasheet: Y:\MIS_DATABASE\DATASHEETS\RESISTORS\RCXXXXL-SER_MAR18.PDF
TP46 TP96 = TESTPOINT: TESTPOINT CIR 20 SMD; Chkd/date: SHREESHAIL/171006; Crtd /date: MAZHAR/171006; Custom_Duty: NA; Customs_HS_Code: NA; Distributor_name: NA; Distributor_part_number: NA; Footprint Path: Y:\MIS_DATABASE\Library\ALTIUM_TOOL\PCB_FOOTPRINTS\Altium_Footprint_Lib.PcbLib; Height: NA; Library Path: Y:\MIS_DATABASE\Library\ALTIUM_TOOL\SCHEMATICS_PARTS\MS_DISCRETE_Library.schlib; MECHANICAL 3D STEP FILE: NA; Mfr_name: LOCAL; Mistral Part No: NA; Package: SMD; Project: BT MODULE_CSRBC04; RoHS: NA; Temperature: NA; Tolerance: NA; Voltage: NA; Wattage: NA; Weight: NA; Datasheet: NA
U91 U114 U116 U118 U124 U3078 U3079 = INA226AIDGS_MSOP10: IC 85V 20BIT POWER/ENERGY/CHARGE MONITOR WITH I2C INTERFACE VSSOP10; Chkd/date: MANIRAJA/041021; Crtd /date: ALVY/011021; Custom_Duty: 15%; Customs_HS_Code: 85423100; Distributor_name: DIGIKEY; Distributor_part_number: 296-INA228AIDGSRCT-ND; Footprint Path: Y:\MIS_DATABASE\Library\ALTIUM_TOOL\PCB_FOOTPRINTS\Altium_Footprint_Lib.PcbLib; Height: 1.10MM; Library Path: Y:\MIS_DATABASE\Library\ALTIUM_TOOL\SCHEMATICS_PARTS\MS_MISCPOWER_Library.schlib; Mfr_name: TEXAS INSTRUMENTS; Mistral Part No: 142021100003-R; Package: VSSOP10; Part_type: ICS\POWER\MANAGEMENT; Project: ENEKOM_SMART SENSOR SYSTEM; RoHS: RoHS; Temperature: -40°C+125°C; Tolerance: NA; Voltage: NA; Wattage: NA; Weight: NA; Datasheet: Y:\MIS_DATABASE\DATASHEETS\ICS\POWER\INA228A.PDF
U92 U113 U115 U119 U123 U3080 U3081 = INA231_DSBGA12: IC HIGH OR LOW SIDE MEASUREMENT BI-DIR CURRENT AND POWER MONITOR WITH 1.8V I2C INTERFACE DSBGA12; Chkd/date: MANIRAJA/250821; Crtd /date: ALVY/250821; Custom_Duty: 15%; Customs_HS_Code: 85423100; Distributor_name: DIGIKEY; Distributor_part_number: 296-49645-1-ND; Footprint Path: Y:\MIS_DATABASE\Library\ALTIUM_TOOL\PCB_FOOTPRINTS\Altium_Footprint_Lib.PcbLib; Height: 0.40MM; Library Path: Y:\MIS_DATABASE\Library\ALTIUM_TOOL\SCHEMATICS_PARTS\MS_MISCPOWER_Library.schlib; Mfr_name: TEXAS INSTRUMENTS; Mistral Part No: 142021080022-R; Package: DSBGA12; Part_type: ICS\POWER\MANAGEMENT; Project: TI_AM62x SVB_BRD; RoHS: RoHS; Temperature: -40°C+125°C; Tolerance: NA; Voltage: NA; Wattage: NA; Weight: 200mg; Datasheet: Y:\MIS_DATABASE\DATASHEETS\ICS\POWER\INA231XXX.PDF
C263 = CAP: CAP CERAMIC 4.7uF 10V 20% X5R AUTO 0402; Chkd/date: MANIRAJA/250221; Crtd /date: ALVY/240221; Custom_Duty: 15%; Customs_HS_Code: 85322990; Distributor_name: MOUSER; Distributor_part_number: 81-GRT155R61A475ME13; Footprint Path: Y:\MIS_DATABASE\Library\ALTIUM_TOOL\PCB_FOOTPRINTS\Altium_Footprint_Lib.PcbLib; Height: 0.65MM; Library Path: Y:\MIS_DATABASE\Library\ALTIUM_TOOL\SCHEMATICS_PARTS\MS_DISCRETE_Library.schlib; Mfr_name: MURATA; Mfr_part_number: GRT155R61A475ME13D; Mistral Part No: 120021020032-R; Package: 0402; Part_type: CAPACITORS\CERAMIC; Project: TI_DRA821 SK EVM BRD; RoHS: RoHS; Temperature: -55°C+85°C; Tolerance: 20%; Voltage: 10V; Wattage: NA; Weight: 1.5mg; Datasheet: Y:\MIS_DATABASE\DATASHEETS\CAPACITORS\GRT155R61A475ME13.PDF
C269 C270 = CAP: CAP CERAMIC 18pF 50V 5% HI-Q C0G(NP0) 0402; Chkd/date: VASANTHA/030315; Crtd /date: NAVEED/271014; Custom_Duty: 15%; Customs_HS_Code: 85322990; Distributor_name: DIGIKEY; Distributor_part_number: 490-3119-1-ND; Footprint Path: Y:\MIS_DATABASE\Library\ALTIUM_TOOL\PCB_FOOTPRINTS\Altium_Footprint_Lib.PcbLib; Height: 0.55MM; Library Path: Y:\MIS_DATABASE\Library\ALTIUM_TOOL\SCHEMATICS_PARTS\MS_DISCRETE_Library.schlib; Mfr_name: MURATA; Mfr_part_number: GJM1555C1H180JB01D; Mistral Part No: 120014100019-R; Package: 0402; Part_type: CAPACITORS\CERAMIC; Project: DC_MIST_RDC; RoHS: RoHS; Temperature: -55°C+125°C; Tolerance: 5%; Voltage: 50V; Wattage: NA; Weight: 6mg; Datasheet: Y:\MIS_DATABASE\DATASHEETS\CAPACITORS\MURATA-GXX-SER_NOV17.PDF
C282 = CAP: CAP CERAMIC 0.1uF 16V 10% X7S AUTO 0201; Alt_Mfr_name: YAGEO AMERICA; Alt_Mfr_part_number: CC0402KRX5R8BB104; Chkd/date: MANIRAJA/110321; Crtd /date: ALVY/110321; Custom_Duty: 15%; Customs_HS_Code: 85322990; Distributor_name: DIGIKEY; Distributor_part_number: 490-GRT033C71C104KE01DTR-ND; Footprint Path: Y:\MIS_DATABASE\Library\ALTIUM_TOOL\PCB_FOOTPRINTS\Altium_Footprint_Lib.PcbLib; Height: 0.33MM; Library Path: Y:\MIS_DATABASE\Library\ALTIUM_TOOL\SCHEMATICS_PARTS\MS_DISCRETE_Library.schlib; Mfr_name: MURATA; Mfr_part_number: GRT033C71C104KE01D; Mistral Part No: 120021030007-R; Package: 0201; Part_type: CAPACITORS\CERAMIC; Project: J7ES_SK_BRD; RoHS: RoHS; Temperature: -55°C+125°C; Tolerance: 10%; Voltage: 16V; Wattage: NA; Weight: 330mg; Datasheet: Y:\MIS_DATABASE\DATASHEETS\CAPACITORS\GRT033C71C104KE01.PDF
C283 = CAP: CAP CERAMIC 0.01uF 25V 10% X5R AUTO 0201; Chkd/date: MANIRAJA/311221; Crtd /date: ALVY/301221; Custom_Duty: 15%; Customs_HS_Code: 85322990; Distributor_name: MOUSER; Distributor_part_number: 81-GRT033R61E103KE1D; Footprint Path: Y:\MIS_DATABASE\Library\ALTIUM_TOOL\PCB_FOOTPRINTS\Altium_Footprint_Lib.PcbLib; Height: 0.33MM; Library Path: Y:\MIS_DATABASE\Library\ALTIUM_TOOL\SCHEMATICS_PARTS\MS_DISCRETE_Library.schlib; Mfr_name: MURATA; Mfr_part_number: GRT033R61E103KE01D; Mistral Part No: 120021120019-R; Package: 0201; Part_type: CAPACITORS\CERAMIC; Project: AM62Q_SKEVM_BRD; RoHS: RoHS; Temperature: -55°C+85°C; Tolerance: 10%; Voltage: 25V; Wattage: NA; Weight: 0.33mg; Datasheet: Y:\MIS_DATABASE\DATASHEETS\CAPACITORS\GRT033R61E103KE01.PDF
C285 = CAP: CAP CERAMIC 2.2uF 25V 10% X5R AUTO 0402; Chkd/date: MANIRAJA/240920; Crtd /date: ALVY/240920; Custom_Duty: 15%; Customs_HS_Code: 85322990; Distributor_name: DIGIKEY; Distributor_part_number: 490-12267-1-ND; Footprint Path: Y:\MIS_DATABASE\Library\ALTIUM_TOOL\PCB_FOOTPRINTS\Altium_Footprint_Lib.PcbLib; Height: 0.70MM; Library Path: Y:\MIS_DATABASE\Library\ALTIUM_TOOL\SCHEMATICS_PARTS\MS_DISCRETE_Library.schlib; Mfr_name: MURATA; Mfr_part_number: GRT155R61E225KE13D; Mistral Part No: 120020090019-R; Package: 0402; Part_type: CAPACITORS\CERAMIC; Project: ECU_RO; RoHS: RoHS; Temperature: -55°C+85°C; Tolerance: 10%; Voltage: 25V; Wattage: NA; Weight: 0.65mg; Datasheet: Y:\MIS_DATABASE\DATASHEETS\CAPACITORS\GRT155R61E225KE13.PDF
C287 = CAP: CAP CERAMIC 10uF 10V 20% X5R 0402; Chkd/date: PRADEEP/130623; Crtd /date: PRADEEP/130623; Custom_Duty: 15%; Customs_HS_Code: 85322990; Distributor_name: NA; Distributor_part_number: NA; Footprint Path: Y:\MIS_DATABASE\Library\ALTIUM_TOOL\PCB_FOOTPRINTS\Altium_Footprint_Lib.PcbLib; Height: 0.55MM; Library Path: Y:\MIS_DATABASE\Library\ALTIUM_TOOL\SCHEMATICS_PARTS\MS_DISCRETE_Library.schlib; Mfr_name: MURATA; Mfr_part_number: GRM155R61A106ME18; Mistral Part No: 120022060018-R; Package: 0402; Part_type: CAPACITORS\CERAMIC; Project: AM62P_SK; RoHS: RoHS; Temperature: -55°C+85°C; Tolerance: 20%; Voltage: 10V; Wattage: NA; Weight: 6mg; Datasheet: Y:\MIS_DATABASE\DATASHEETS\CAPACITORS\MURATA-GXX-SER_NOV17.PDF
D3 = DIODE_SOD323: DIODE 1CH ESD PROTECTION X1SON2; Chkd/date: MANIRAJA/040420; Crtd /date: VASANTHA/181114; Custom_Duty: 15%; Customs_HS_Code: 85423100; Distributor_name: DIGIKEY; Distributor_part_number: 296-30406-1-ND; Footprint Path: Y:\MIS_DATABASE\Library\ALTIUM_TOOL\PCB_FOOTPRINTS\Altium_Footprint_Lib.PcbLib; Height: 0.45MM; Library Path: Y:\MIS_DATABASE\Library\ALTIUM_TOOL\SCHEMATICS_PARTS\MS_DISCRETE_Library.schlib; Mfr_name: TEXAS INSTRUMENTS; Mistral Part No: 130014110022-R; Package: X1SON2; Part_type: DIODE; Project: GALILEO_EVM; RoHS: RoHS; Temperature: -40°C+125°C; Tolerance: NA; Voltage: NA; Wattage: NA; Weight: 1mg; Datasheet: Y:\MIS_DATABASE\DATASHEETS\ICS\INTERFACE\TPD1E10B06-SER.PDF
FL17 FL18 = EMIFILTER_IND: IND FERRITE BEAD CHIP 120E 2A 0402; Chkd/date: MANIRAJA/311221; Crtd /date: ALVY/301221; Custom_Duty: 24%; Customs_HS_Code: 85437099; Distributor_name: NA; Distributor_part_number: NA; Footprint Path: Y:\MIS_DATABASE\Library\ALTIUM_TOOL\PCB_FOOTPRINTS\Altium_Footprint_Lib.PcbLib; Height: 0.55MM; Library Path: Y:\MIS_DATABASE\Library\ALTIUM_TOOL\SCHEMATICS_PARTS\MS_FILTER_Library.schlib; Mfr_name: MURATA; Mfr_part_number: BLM15PX121SZ1B; Mistral Part No: 130021120017-R; Package: 0402; Part_type: INDUCTOR; Project: AM62Q_SKEVM_BRD; RoHS: RoHS; Temperature: -55°C+125°C; Tolerance: 25%; Voltage: NA; Wattage: NA; Weight: 1mg; Datasheet: Y:\MIS_DATABASE\DATASHEETS\DISCRETES\INDUCTORS\BLM-SER.PDF
J22 = CON_USB_MINI-B: CON MICRO USB TYPE B 5POS FEMALE RT SMD; Chkd/date: MANIRAJA/150519; Crtd /date: ALVY/150519; Custom_Duty: 24%; Customs_HS_Code: 85369090; Distributor_name: DIGIKEY; Distributor_part_number: 732-5960-1-ND; Footprint Path: Y:\MIS_DATABASE\Library\ALTIUM_TOOL\PCB_FOOTPRINTS\Altium_Footprint_Lib.PcbLib; Height: 2.66MM; Library Path: Y:\MIS_DATABASE\Library\ALTIUM_TOOL\SCHEMATICS_PARTS\MS_CONNECTOR_Library.schlib; Mfr_name: WURTH ELECTRONICS; Mfr_part_number: 629105150521; Mistral Part No: 150019050015-R; Package: SMD; Part_type: CONNECTOR\USB; Project: NEXTNAV_ALT-STATION_ATE_BRD; RoHS: RoHS; Temperature: -40°C+85°C; Tolerance: NA; Voltage: NA; Wattage: NA; Weight: 360mg; Datasheet: Y:\MIS_DATABASE\DATASHEETS\CONNECTORS\629105150521.PDF
LD7 = DIODE_LED: DIODE LED BRIGHT GREEN SMD; Chkd/date: MANIRAJA/180820; Crtd /date: ALVY/180820; Custom_Duty: 24%; Customs_HS_Code: 85439000; Distributor_name: DIGIKEY; Distributor_part_number: 732-4986-1-ND; Footprint Path: Y:\MIS_DATABASE\Library\ALTIUM_TOOL\PCB_FOOTPRINTS\Altium_Footprint_Lib.PcbLib; Height: 0.80MM; Library Path: Y:\MIS_DATABASE\Library\ALTIUM_TOOL\SCHEMATICS_PARTS\MS_OPTO_Library.schlib; Mfr_name: WURTH ELECTRONICS; Mistral Part No: 130020080012-R; Package: SMD; Part_type: OPTO\LED; Project: AM64x_EVM_BRD; RoHS: RoHS; Temperature: -40°C+85°C; Tolerance: NA; Voltage: NA; Wattage: NA; Weight: 10mg; Datasheet: Y:\MIS_DATABASE\DATASHEETS\DISCRETES\LEDS\150080VS75000.PDF
R323 = RESISTOR: RES 2.2K 1/20W 5% 0201; Chkd/date: MANIRAJA/050517; Crtd /date: MANIRAJA/050517; Custom_Duty: 15%; Customs_HS_Code: 85332119; Distributor_name: DIGIKEY; Distributor_part_number: 311-2.2KNCT-ND; Footprint Path: Y:\MIS_DATABASE\Library\ALTIUM_TOOL\PCB_FOOTPRINTS\Altium_Footprint_Lib.PcbLib; Height: 0.26MM; Library Path: Y:\MIS_DATABASE\Library\ALTIUM_TOOL\SCHEMATICS_PARTS\MS_DISCRETE_Library.schlib; Mfr_name: YAGEO AMERICA; Mfr_part_number: RC0201JR-072K2L; Mistral Part No: 110009030427-R; Package: 0201; Part_type: RESISTORS\FIXED; Project: GOLDEN-I LITE; RoHS: RoHS; Temperature: -55°C+125°C; Tolerance: 5%; Voltage: NA; Wattage: 1/20W; Weight: 0.17mg; Datasheet: Y:\MIS_DATABASE\DATASHEETS\RESISTORS\RCXXXXL-SER_MAR18.PDF
R330 = RESISTOR: RES 220E 1/10W 5% 0402; Chkd/date: VASANTHA/291216; Crtd /date: GEETHA/260406; Custom_Duty: 15%; Customs_HS_Code: 85332119; Distributor_name: DIGIKEY; Distributor_part_number: P220JCT-ND; Footprint Path: Y:\MIS_DATABASE\Library\ALTIUM_TOOL\PCB_FOOTPRINTS\Altium_Footprint_Lib.PcbLib; Height: 0.40MM; Library Path: Y:\MIS_DATABASE\Library\ALTIUM_TOOL\SCHEMATICS_PARTS\MS_DISCRETE_Library.schlib; Mfr_name: PANASONIC-ECG; Mfr_part_number: ERJ-2GEJ221X; Mistral Part No: 110009030506-R; Package: 0402; Part_type: RESISTORS\FIXED; Project: RED EYE; RoHS: RoHS; Temperature: -55°C+155°C; Tolerance: 5%; Voltage: NA; Wattage: 1/10W; Weight: 0.8mg; Datasheet: Y:\MIS_DATABASE\DATASHEETS\RESISTORS\PAN-ERJSER_NOV17.PDF
R385 = RESISTOR: RES 0E 1/8W 5% 0805; Chkd/date: VASANTHA/130416; Crtd /date: JEBRAN/020316; Custom_Duty: 15%; Customs_HS_Code: 85332119; Distributor_name: DIGIKEY; Distributor_part_number: 311-0.0ARCT-ND; Footprint Path: Y:\MIS_DATABASE\Library\ALTIUM_TOOL\PCB_FOOTPRINTS\Altium_Footprint_Lib.PcbLib; Height: 0.60MM; Library Path: Y:\MIS_DATABASE\Library\ALTIUM_TOOL\SCHEMATICS_PARTS\MS_DISCRETE_Library.schlib; Mfr_name: YAGEO AMERICA; Mfr_part_number: RC0805JR-070RL; Mistral Part No: 110009030074-R; Package: 0805; Part_type: RESISTORS\FIXED; Project: ZK_BIOMETRIC; RoHS: RoHS; Temperature: -55°C+155°C; Tolerance: 5%; Voltage: NA; Wattage: 1/8W; Weight: 5.5mg; Datasheet: Y:\MIS_DATABASE\DATASHEETS\RESISTORS\RCXXXXL-SER_MAR18.PDF
R609 = RESISTOR: RES 12K 1/10W 1% 0402; Chkd/date: VASANTHA/041215; Crtd /date: VASANTHA/041215; Custom_Duty: 15%; Customs_HS_Code: 85332119; Distributor_name: DIGIKEY; Distributor_part_number: P12.0KLCT-ND; Footprint Path: Y:\MIS_DATABASE\Library\ALTIUM_TOOL\PCB_FOOTPRINTS\Altium_Footprint_Lib.PcbLib; Height: 0.40MM; Library Path: Y:\MIS_DATABASE\Library\ALTIUM_TOOL\SCHEMATICS_PARTS\MS_DISCRETE_Library.schlib; Mfr_name: PANASONIC-ECG; Mfr_part_number: ERJ-2RKF1202X; Mistral Part No: 110019040053-R; Package: 0402; Part_type: RESISTORS\FIXED; Project: TI_C5545; RoHS: RoHS; Temperature: -55°C+155°C; Tolerance: 1%; Voltage: NA; Wattage: 1/10W; Weight: 0.8mg; Datasheet: Y:\MIS_DATABASE\DATASHEETS\RESISTORS\PAN-ERJSER_NOV17.PDF
U61 = 93LC46B_MSOP8: IC 1K MICROWIRE COMPATIBLE SERIAL EEPROM MSOP8; Chkd/date: MANIRAJA/150218; Crtd /date: ALVY/150218; Custom_Duty: 15%; Customs_HS_Code: 85423100; Distributor_name: DIGIKEY; Distributor_part_number: 93LC46B-I/MS-ND; Footprint Path: Y:\MIS_DATABASE\Library\ALTIUM_TOOL\PCB_FOOTPRINTS\Altium_Footprint_Lib.PcbLib; Height: 1.10MM; Library Path: Y:\MIS_DATABASE\Library\ALTIUM_TOOL\SCHEMATICS_PARTS\MS_MISCMEMORY_Library.schlib; Mfr_name: MICROCHIP; Mfr_part_number: 93LC46B-I/MS; Mistral Part No: 141118020002-R; Package: MSOP8; Part_type: ICS\DIGITAL\MEMORY; Project: TI_MAXIE_CPB; RoHS: RoHS; Temperature: -40°C+85°C; Tolerance: NA; Voltage: NA; Wattage: NA; Weight: 140mg; Datasheet: Y:\MIS_DATABASE\DATASHEETS\ICS\MEMORY\93LC46B.PDF
U64 = FT4232H_LQFP64: IC HIGH SPEED QUAD USB UART LQFP64; Chkd/date: MANIRAJA/110917; Crtd /date: VIJAYALAKSHMI/120813; Custom_Duty: 15%; Customs_HS_Code: 85423100; Distributor_name: DIGIKEY; Distributor_part_number: 768-1026-1-ND; Footprint Path: Y:\MIS_DATABASE\Library\ALTIUM_TOOL\PCB_FOOTPRINTS\Altium_Footprint_Lib.PcbLib; Height: 1.60MM; Library Path: Y:\MIS_DATABASE\Library\ALTIUM_TOOL\SCHEMATICS_PARTS\MS_COMBINATIONAL_Library.schlib; Mfr_name: FTDI; Mfr_part_number: FT4232HL-REEL; Mistral Part No: 141013080006-R; Package: LQFP64; Part_type: ICS\DIGITAL\PERIPHERAL; Project: DM37XX; RoHS: RoHS; Temperature: -40°C+85°C; Tolerance: NA; Voltage: NA; Wattage: NA; Weight: 342.7mg; Datasheet: Y:\MIS_DATABASE\DATASHEETS\ICS\DIGITAL\PERIPHERAL\FT4232HX.PDF
U66 = TPS73501DRVR_SON6: IC 500mA LOW DROPOUT REGULATOR SON6; Chkd/date: VASANTHA/280915; Crtd /date: NAVEED/011014; Custom_Duty: 15%; Customs_HS_Code: 85423100; Distributor_name: DIGIKEY; Distributor_part_number: TPS73533DRVR-ND; Height: 0.80MM; Mfr_name: TEXAS INSTRUMENTS; Mistral Part No: 142014100001-R; Package: SON6; Part_type: ICS\POWER\VOLTAGE REGULATOR; Project: BLUETOOTH_WATCH; RoHS: RoHS; Temperature: -40°C+125°C; Tolerance: NA; Voltage: NA; Wattage: NA; Weight: NA; Datasheet: Y:\MIS_DATABASE\DATASHEETS\ICS\POWER\TPS735.PDF
U67 = TPD2E001DRLR_SOT-5: IC ESD-PROTECTION DIODE ARRAYS SOT-5; Chkd/date: NAVEED/150714; Crtd /date: MUDDU/250510; Custom_Duty: 15%; Customs_HS_Code: 85423100; Distributor_name: DIGIKEY; Distributor_part_number: 296-21883-1-ND; Footprint Path: Y:\MIS_DATABASE\Library\ALTIUM_TOOL\PCB_FOOTPRINTS\Altium_Footprint_Lib.PcbLib; Height: 0.60MM; Library Path: Y:\MIS_DATABASE\Library\ALTIUM_TOOL\SCHEMATICS_PARTS\MS_FILTER_Library.schlib; Mfr_name: TEXAS INSTRUMENTS; Mistral Part No: 140110060007-R; Package: SOT-5; Part_type: ICS\ANALOG\ACTIVE FILTER; Project: CENTAURUS; RoHS: RoHS; Temperature: -40°C+85°C; Tolerance: NA; Voltage: NA; Wattage: NA; Weight: 2.8mg; Datasheet: Y:\MIS_DATABASE\DATASHEETS\ICS\MISC\TPD2E001DRLR.PDF
Y6 = CRY: CRY 12.000MHz 18pF SMD; Chkd/date: MANIRAJA/310818; Crtd /date: MANIRAJA/310818; Custom_Duty: 24%; Customs_HS_Code: 85439000; Distributor_name: DIGIKEY; Distributor_part_number: CTX1170CT-ND; Footprint Path: Y:\MIS_DATABASE\Library\ALTIUM_TOOL\PCB_FOOTPRINTS\Altium_Footprint_Lib.PcbLib; Height: 1.35MM; Library Path: Y:\MIS_DATABASE\Library\ALTIUM_TOOL\SCHEMATICS_PARTS\MS_DISCRETE_Library.schlib; Mfr_name: CTS; Mfr_part_number: 445I23D12M00000; Mistral Part No: 130018080040-R; Package: SMD; Part_type: CRYSTAL; Project: TI_MAXIE_CPB; RoHS: RoHS; Temperature: -40°C+85°C; Tolerance: NA; Voltage: NA; Wattage: NA; Weight: 50mg; Datasheet: Y:\MIS_DATABASE\DATASHEETS\MISC\CRY_OSC\445.PDF

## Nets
DGND: C262.1 C263.2 C264.1 C269.2 C270.2 C275.1 C280.1 C281.1 C282.1 C283.1 C285.2 C287.1 C288.1 C289.1 C291.1 C295.2 C427.2 C525.2 C560.2 C598.2 C599.1 C604.2 C606.1 C607.1 C3732.1 C3733.2 C3762.2 C3764.2 D3.1 J22.5(GND) J33.2 R385.1 R609.1 R5745.1 U61.5(VSS) U64.1(GND1) U64.5(GND2) U64.10(AGND) U64.11(GND3) U64.13(TEST) U64.15(GND4) U64.25(GND5) U64.35(GND6) U64.47(GND7) U64.51(GND8) U66.3(GND) U66.7(EP) U67.4(GND) U91.7(GND) U92.C1(GND) U113.B3(A0) U113.C1(GND) U113.C3(A1) U114.1(A1) U114.2(A0) U114.7(GND) U115.C1(GND) U115.C3(A1) U116.1(A1) U116.7(GND) U118.7(GND) U119.C1(GND) U123.C1(GND) U124.7(GND) U2357.5(GND) U2358.4(GND) U3078.1(A1) U3078.7(GND) U3079.1(A1) U3079.7(GND) U3080.C1(GND) U3080.C3(A1) U3081.C1(GND) U3081.C3(A1) ; also on sheet 1 2 12 13 14 15 16 17 18 19 20 21 22 23 24 25 26 27 28 29 31 32 33 34 35 36 37 38 39 40 41 42 43 44 45 46 47 52 53 54 55 56
DVDD1V8_ALERT: R305.1 U123.A3(ALERT) U124.3(ALERT)
DVDD3V3_ALERT: R505.1 U91.3(ALERT) U92.A3(ALERT)
DVDD3V3_N: R539.2 ; also on sheet 16
DVDD3V3_P: R540.2 ; also on sheet 16
VCC1V8_SYS: C3733.1 R5744.2 R5746.2 U2358.8(VCC) ; also on sheet 16 21 22 23 24 26 27 28 29 31 34 38 39 40 42 43 44 46 47 52 54 56
VCC1V8_SYS_N: R335.2 ; also on sheet 16
VCC1V8_SYS_P: R331.2 ; also on sheet 16
VCC_1V8_FT4232: C263.1 C280.2 C281.2 C599.2 U64.12(VCORE) U64.37(VCORE) U64.49(VREGOUT) U64.64(VCORE)
VCC_3V3_FT4232: C262.2 C264.2 C275.2 C285.1 C288.2 C289.2 FL17.2 FL18.2 LD7.2(ANODE) R321.2 R328.2 R333.2 U61.8(VCC) U64.20(VCCIO) U64.31(VCCIO) U64.42(VCCIO) U64.50(VREGIN) U64.56(VCCIO) U66.1(OUT) ; also on sheet 52
VCC_3V3_SYS: C427.1 C525.1 C560.1 C598.1 C604.1 C3732.2 C3762.1 C3764.1 R597.2 R5741.1 R5742.1 U91.1(A1) U91.6(VS) U92.B1(VS) U92.C3(A1) U113.B1(VS) U114.6(VS) U115.B1(VS) U115.B3(A0) U116.2(A0) U116.6(VS) U118.2(A0) U118.6(VS) U119.B1(VS) U119.B3(A0) U123.B1(VS) U123.B3(A0) U123.C3(A1) U124.1(A1) U124.2(A0) U124.6(VS) U2357.1(V+) U3078.6(VS) U3079.6(VS) U3080.B1(VS) U3081.B1(VS) ; also on sheet 1 2 12 16 17 23 28 29 31 34 35 36 38 40 44 47 55 56
VCC_CORE_N: R572.2 ; also on sheet 16
VCC_CORE_P: R571.2 ; also on sheet 16
VDD_0V85_N: R585.2 ; also on sheet 16
VDD_0V85_P: R584.2 ; also on sheet 16
VDD_1V8_N: R311.2 ; also on sheet 16
VDD_1V8_P: R310.2 ; also on sheet 16
VDD_CANUART_ALERT: R5778.1 U3078.3(ALERT) U3080.A3(ALERT)
VDD_CANUART_N: R5780.2 ; also on sheet 15
VDD_CANUART_P: R5781.2 ; also on sheet 15
VDD_CORE_ALERT: R586.1 U113.A3(ALERT) U114.3(ALERT)
VDD_CORE_N: C524.2 R572.1 U113.D1(BUS) U113.D2(IN-) U114.8(VBUS) U114.9(IN-)
VDD_CORE_P: C524.1 R571.1 U113.D3(IN+) U114.10(IN+)
VDDA_1V8_ALERT: R608.1 U118.3(ALERT) U119.A3(ALERT)
VDDA_1V8_N: C597.2 R311.1 U118.8(VBUS) U118.9(IN-) U119.D1(BUS) U119.D2(IN-)
VDDA_1V8_P: C597.1 R310.1 U118.10(IN+) U119.D3(IN+)
VDDR_CORE_ALERT: R596.1 U115.A3(ALERT) U116.3(ALERT)
VDDR_CORE_N: C559.2 R585.1 U115.D1(BUS) U115.D2(IN-) U116.8(VBUS) U116.9(IN-)
VDDR_CORE_P: C559.1 R584.1 U115.D3(IN+) U116.10(IN+)
VDDSHV_CANUART_ALERT: R5782.1 U3079.3(ALERT) U3081.A3(ALERT)
VDDSHV_CANUART_N: R5784.2 ; also on sheet 15
VDDSHV_CANUART_P: R5785.2 ; also on sheet 15
EEPROM_A1: R5745.2 U2358.2(A1)
EEPROM_A2: R5744.1 U2358.3(A2)
EEPROM_WP: J33.1 R5746.1 U2358.7(WP)
FT4232_DO: R321.1 R323.2 U61.4(DO)
FT4232_EECLK: R328.1 U61.2(CLK) U64.62(EECLK)
FT4232_EECS: R333.1 U61.1(CS) U64.63(EECS)
FT4232_EEDATA: R323.1 U61.3(DI) U64.61(EEDATA)
FT4232_REF: R609.2 U64.6(REF)
FT4232_RESET: C282.2 R357.1 U64.14(~{RESET})
FT4232_SOC_UART2_RX_3V3: U64.16(ADBUS0) ; also on sheet 52
FT4232_SOC_UART2_TX_3V3: U64.17(ADBUS1) ; also on sheet 52
FT4232_SOC_UART3_RX_3V3: U64.26(BDBUS0) ; also on sheet 52
FT4232_SOC_UART3_TX_3V3: U64.27(BDBUS1) ; also on sheet 52
FT4232_USB_DM: J22.2(D-) U64.7(DM) U67.5(IO2)
FT4232_USB_DP: J22.3(D+) U64.8(DP) U67.3(IO1)
FT4232_USB_VBUS: C287.2 C291.2 C295.1 D3.2 J22.1(VBUS) TP96.1(TP) U66.4(EN) U66.6(IN) U67.1(VCC)
FT4232_WKUP_UART0_CTSN_3V3: U64.40(CDBUS2) ; also on sheet 52
FT4232_WKUP_UART0_RTSN_3V3: U64.41(CDBUS3) ; also on sheet 52
FT4232_WKUP_UART0_RXD_3V3: U64.38(CDBUS0) ; also on sheet 52
FT4232_WKUP_UART0_TXD_3V3: U64.39(CDBUS1) ; also on sheet 52
FT_PWREN#: R330.1 U64.60(~{PWREN})
I2C0_SCL_1V8: U2358.6(SCL) ; also on sheet 16 22 31 38 39 40 41 47
I2C0_SDA_1V8: U2358.5(SDA) ; also on sheet 16 22 31 38 39 40 41 47
INA_ALERT: R305.2 R505.2 R586.2 R596.2 R597.1 R608.2 R5778.2 R5782.2 TP46.1(TP)
SoC_DVDD1V8_N: C603.2 R335.1 U123.D1(BUS) U123.D2(IN-) U124.8(VBUS) U124.9(IN-)
SoC_DVDD1V8_P: C603.1 R331.1 U123.D3(IN+) U124.10(IN+)
SoC_DVDD3V3_N: C428.2 R539.1 U91.8(VBUS) U91.9(IN-) U92.D1(BUS) U92.D2(IN-)
SoC_DVDD3V3_P: C428.1 R540.1 U91.10(IN+) U92.D3(IN+)
SoC_I2C0_SCL: U91.2(A0) U91.5(SCL) U92.A1(SCL) U92.B3(A0) U113.A1(SCL) U114.5(SCL) U115.A1(SCL) U116.5(SCL) U118.1(A1) U118.5(SCL) U119.A1(SCL) U119.C3(A1) U123.A1(SCL) U124.5(SCL) U2357.8(SCL) U3078.5(SCL) U3079.2(A0) U3079.5(SCL) U3080.A1(SCL) U3081.A1(SCL) U3081.B3(A0) ; also on sheet 12 35 36 47 55
SoC_I2C0_SDA: U91.4(SDA) U92.A2(SDA) U113.A2(SDA) U114.4(SDA) U115.A2(SDA) U116.4(SDA) U118.4(SDA) U119.A2(SDA) U123.A2(SDA) U124.4(SDA) U2357.7(SDA) U3078.2(A0) U3078.4(SDA) U3079.4(SDA) U3080.A2(SDA) U3080.B3(A0) U3081.A2(SDA) ; also on sheet 12 35 36 47 55
SOC_VDD_CANUART_N: C3761.2 R5780.1 U3078.8(VBUS) U3078.9(IN-) U3080.D1(BUS) U3080.D2(IN-)
SoC_VDD_CANUART_P: C3761.1 R5781.1 U3078.10(IN+) U3080.D3(IN+)
SOC_VDDSHV_CANUART_N: C3763.2 R5784.1 U3079.8(VBUS) U3079.9(IN-) U3081.D1(BUS) U3081.D2(IN-)
SOC_VDDSHV_CANUART_P: C3763.1 R5785.1 U3079.10(IN+) U3081.D3(IN+)
TMP411_ALERT: R5741.2 U2357.6(~{ALERT}/~{THERM2})
TMP411_THERM: R5742.2 U2357.4(~{THERM})
UART_SHIELD: J22.6(SH1) J22.7(SH2) J22.8(SH3) J22.9(SH4) R385.2
VPHY_3V3_FT4232: C606.2 FL17.1 U64.4(VPHY)
VPLL_3V3_FT4232: C607.2 FL18.1 R357.2 U64.9(VPLL)
N16856152: C270.1 U64.3(OSCO) Y6.2
N16856224: C269.1 U64.2(OSCI) Y6.1
N16857368: C283.2 U66.2(NR/FB)
N17378539: LD7.1(CATHODE) R330.2
N28133286: R5743.1 U2357.2(D+)
N28133288: R5743.2 U2357.3(D-)

Not connected (* = marked no-connect by the designer): J22 4(ID)*; U61 6(NC1)* 7(NC2)*; U64 18(ADBUS2)* 19(ADBUS3)* 21(ADBUS4)* 22(ADBUS5)* 23(ADBUS6)* 24(ADBUS7)* 28(BDBUS2)* 29(BDBUS3)* 30(BDBUS4)* 32(BDBUS5)* 33(BDBUS6)* 34(BDBUS7)* 36(~{SUSPEND})* 43(CDBUS4)* 44(CDBUS5)* 45(CDBUS6)* 46(CDBUS7)* 48(DDBUS0)* 52(DDBUS1)* 53(DDBUS2)* 54(DDBUS3)* 55(DDBUS4)* 57(DDBUS5)* 58(DDBUS6)* 59(DDBUS7)*; U66 5(NC)*; U67 2(NC)*; U92 B2(NC1)* C2(NC2)*; U113 B2(NC1)* C2(NC2)*; U115 B2(NC1)* C2(NC2)*; U119 B2(NC1)* C2(NC2)*; U123 B2(NC1)* C2(NC2)*; U2358 1(NC)*; U3080 B2(NC1)* C2(NC2)*; U3081 B2(NC1)* C2(NC2)*

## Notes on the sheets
sheet 48
- TEMPERATURE SENSORS
- Note: D+ and D- Shorted as
  TEMPCAL is not used
- I2C Addr: 0X4C
- CAD Note: Place Close To SOC
- BOARD ID EEPROM
- EEPROM Address - 0x54
- Short with a
  Jumper to perform
  write operation
- PROC180E1
sheet 49
- CURRENT MONITORING DEVICES - 1
- SoC_DVDD1V8
- VDD_CORE
- I2C ADDRESS: 0x40
- I2C ADDRESS: 0x45
- VDDR_CORE
- VDDA_1V8
- I2C ADDRESS: 0x4D
- I2C ADDRESS: 0x41
- VDD_CANUART
- SoC_DVDD3V3
- I2C ADDRESS: 0x42
- I2C ADDRESS: 0x47
- VDDSHV_CANUART
- INA I2C SLAVE ADDRESS
- SLAVE
  ADDRESS
  (IN HEX)
- POWER SOURCE
- SUPPLY NET
- VCC_CORE
- VDD_CORE
- 40
- VCC_0V85
- VDDR_CORE
- 41
- VCC_3V3_SYS
- SoC_DVDD3V3
- 47
- VCC_1V8
- SoC_DVDD1V8
- 45
- I2C ADDRESS: 0x43
- VDDA1V8
- VDDA_1V8
- 4D
- VDD_CANUART
- SOC_VDD_CANUART
- 42
- VDDSHV_CANUART
- SOC_VDDSHV_CANUART
- 43
- Note: The design supports current/voltage measurements
  using either INA228 or INA231.
  INA228 will be populated on the the SK
  (Implemented via stacked PCB footprint).
- PROC180E1
sheet 50
- CURRENT MONITORING DEVICES - 2
- VDD_CORE
- SoC_DVDD1V8
- I2C ADDRESS: 0x40
- I2C ADDRESS: 0x45
- VDDR_CORE
- VDDA_1V8
- I2C ADDRESS: 0x41
- I2C ADDRESS: 0x4D
- SoC_DVDD3V3
- VDD_CANUART
- I2C ADDRESS: 0x47
- I2C ADDRESS: 0x42
- VDDSHV_CANUART
- INA I2C SLAVE ADDRESS
- SLAVE
  ADDRESS
  (IN HEX)
- POWER SOURCE
- SUPPLY NET
- VCC_CORE
- VDD_CORE
- 40
- VCC_0V85
- VDDR_CORE
- 41
- VCC_3V3_SYS
- SoC_DVDD3V3
- 47
- VCC_1V8
- SoC_DVDD1V8
- 45
- VDDA1V8
- VDDA_1V8
- 4D
- VDD_CANUART
- SOC_VDD_CANUART
- 42
- I2C ADDRESS: 0x43
- VDDSHV_CANUART
- SOC_VDDSHV_CANUART
- 43
- Note: The design supports current/voltage measurements
  using either INA228 or INA231.
  INA228 will be populated on the the SK
  (Implemented via stacked PCB footprint).
- PROC180E1
sheet 51
- USB TO UART BRIDGE
- EEPROM
- Silk: UART
- 90E
- 5V to 3.3V@500mA LDO
